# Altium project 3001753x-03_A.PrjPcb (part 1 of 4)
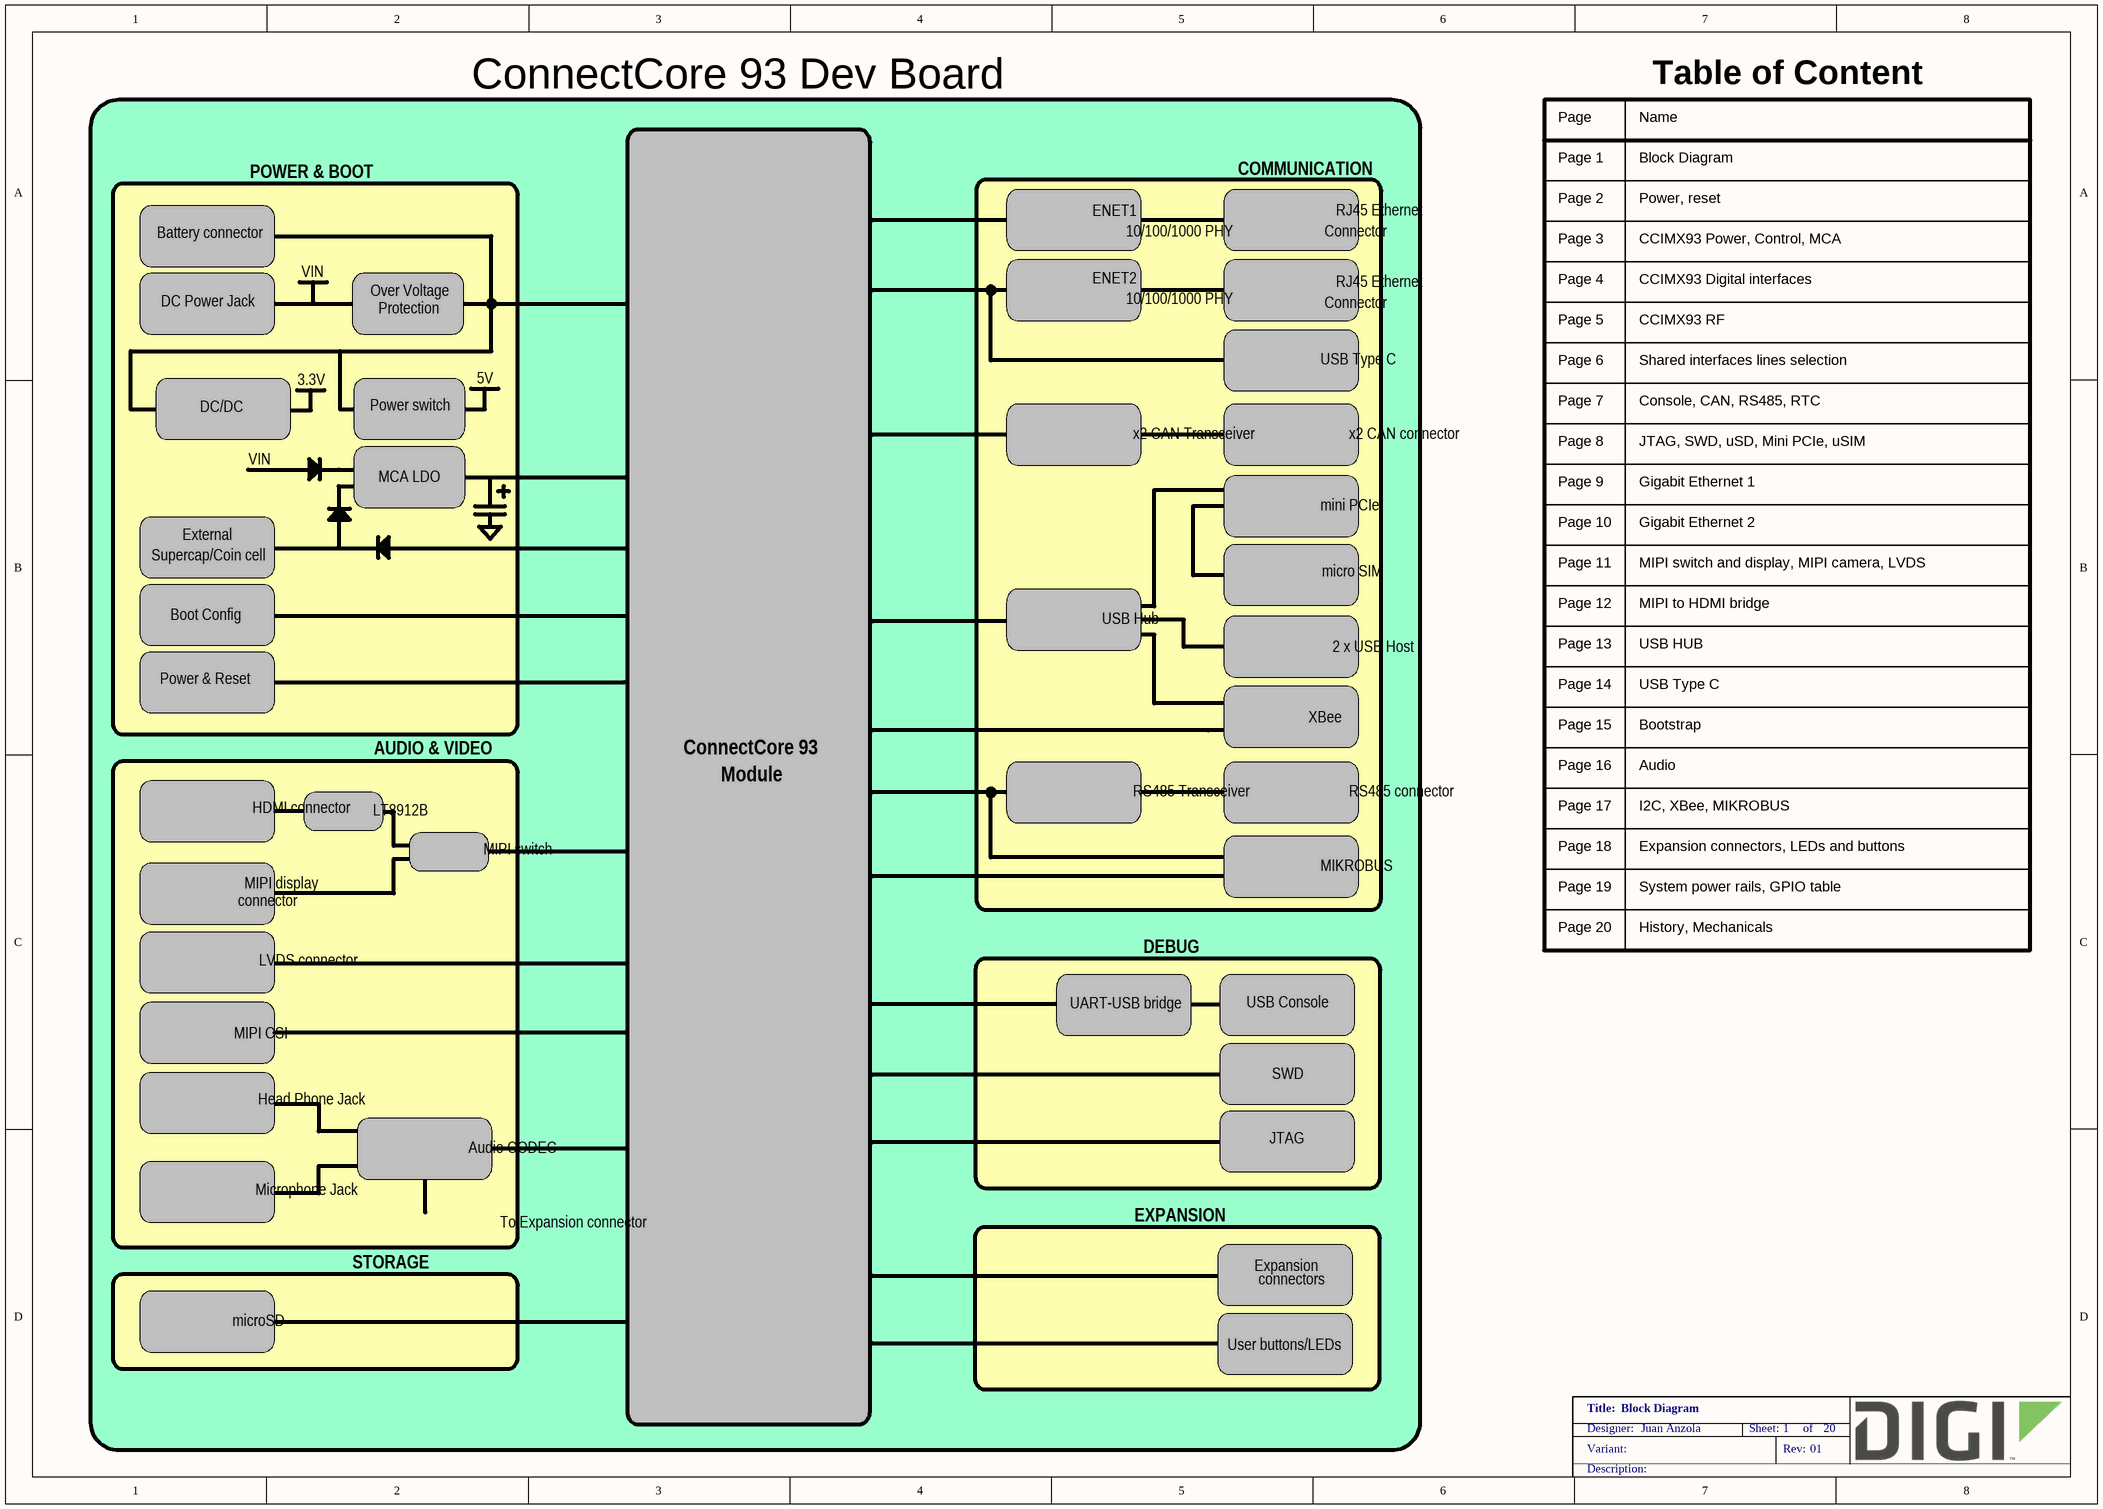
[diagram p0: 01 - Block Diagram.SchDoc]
VariantRevision: 01
20 sheets, 677 parts. Net scope: flat (ports and power ports of the same name join across sheets).
Board files: 3001753x-03_A.PcbDoc, 3001753x-03_A_IND.PcbDoc, 3001753x-03_A_PANEL.PcbDoc
Sheets:
  01 - Block Diagram.SchDoc
  02 - Power, reset.SchDoc
  03 - CCIMX93 Power, Control, MCA.SchDoc
  04 - CCIMX93 Digital interfaces.SchDoc
  05 - CCIMX93 RF.SchDoc
  06 - Shared interfaces lines selection.SchDoc
  07 - Console, CAN, RS485, RTC.SchDoc
  08 - JTAG, SWD, uSD, Mini PCIe, uSIM.SchDoc
  09 - Gigabit Ethernet 1.SchDoc
  10 - Gigabit Ethernet 2.SchDoc
  11 - MIPI switch and display, MIPI camera, LVDS.SchDoc
  12 - MIPI to HDMI bridge.SchDoc
  13 - USB HUB.SchDoc
  14 - USB Type C.SchDoc
  15 - Bootstrap.SchDoc
  16 - Audio.SchDoc
  17 - I2C, XBee, MIKROBUS.SchDoc
  18 - Expansion connectors, LEDs and buttons.SchDoc
  19 - System power rails, GPIO table.SchDoc
  20 - History, Mechanicals.SchDoc

## Sheet 01 - Block Diagram.SchDoc: Block Diagram
size A3; PageSetup: Record=PageOptions¦CenterHorizontal=True¦CenterVertical=True¦PrintScale=0.70¦XCorrection=1.00¦YCorrection=1.00¦PrintKind=0¦BorderSize=5000000¦LeftOffset=0¦BottomOffset=0¦Orientation=2¦PaperLength=4200¦PaperWidth=2970¦Scale=100¦PaperSource=7¦PrintQuality=600¦MediaType=1¦DitherType=10¦PaperKind=A4¦PrintScaleMode=1; Author: Juan Anzola; SheetNumber: 1; SheetTotal: 20

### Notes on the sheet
- ConnectCore 93 Dev Board
- Table of Content
- POWER & BOOT
- COMMUNICATION
- Page 1
- Page
- Block Diagram
- Name
- Battery connector
- ENET1
- 10/100/1000 PHY
- Connector
- RJ45 Ethernet
- Page 2
- Page 3
- Power, reset
- CCIMX93 Power, Control, MCA
- DC Power Jack
- VIN
- Protection
- Over Voltage
- ENET2
- Page 4
- CCIMX93 Digital interfaces
- 5V
- USB Type C
- Page 5
- Page 6
- CCIMX93 RF
- Shared interfaces lines selection
- DC/DC
- 3.3V
- Power switch
- x2 CAN Transceiver
- x2 CAN connector
- Page 7
- Page 8
- JTAG, SWD, uSD, Mini PCIe, uSIM
- Console, CAN, RS485, RTC
- MCA LDO
- mini PCIe
- Page 9
- Gigabit Ethernet 1
- Supercap/Coin cell
- External
- micro SIM
- Page 10
- Page 11
- Gigabit Ethernet 2
- MIPI switch and display, MIPI camera, LVDS
- Boot Config
- USB Hub
- 2 x USB Host
- Page 12
- Page 13
- USB HUB
- MIPI to HDMI bridge
- Power & Reset
- XBee
- Page 14
- AUDIO & VIDEO
- ConnectCore 93
- Module
- Page 15
- Page 16
- Audio
- Bootstrap
- HDMI connector
- LT8912B
- MIPI switch
- RS485 Transceiver
- RS485 connector
- Page 17
- Page 18
- I2C, XBee, MIKROBUS
- Expansion connectors, LEDs and buttons
- connector
- MIPI display
- MIKROBUS
- Page 19
- System power rails, GPIO table
- LVDS connector
- DEBUG
- Page 20
- History, Mechanicals
- MIPI CSI
- UART-USB bridge
- USB Console
- Head Phone Jack
- SWD
- Audio CODEC
- JTAG
- Microphone Jack
- To Expansion connector
- EXPANSION
- microSD
- STORAGE
- Expansion
- connectors
- User buttons/LEDs

## Sheet 02 - Power, reset.SchDoc: Power, reset
size A3; PageSetup: Record=PageOptions¦CenterHorizontal=True¦CenterVertical=True¦PrintScale=0.70¦XCorrection=1.00¦YCorrection=1.00¦PrintKind=0¦BorderSize=5000000¦LeftOffset=0¦BottomOffset=0¦Orientation=2¦PaperLength=4200¦PaperWidth=2970¦Scale=100¦PaperSource=7¦PrintQuality=600¦MediaType=1¦DitherType=10¦PaperKind=A4¦PrintScaleMode=1; Author: Juan Anzola; SheetNumber: 2; SheetTotal: 20
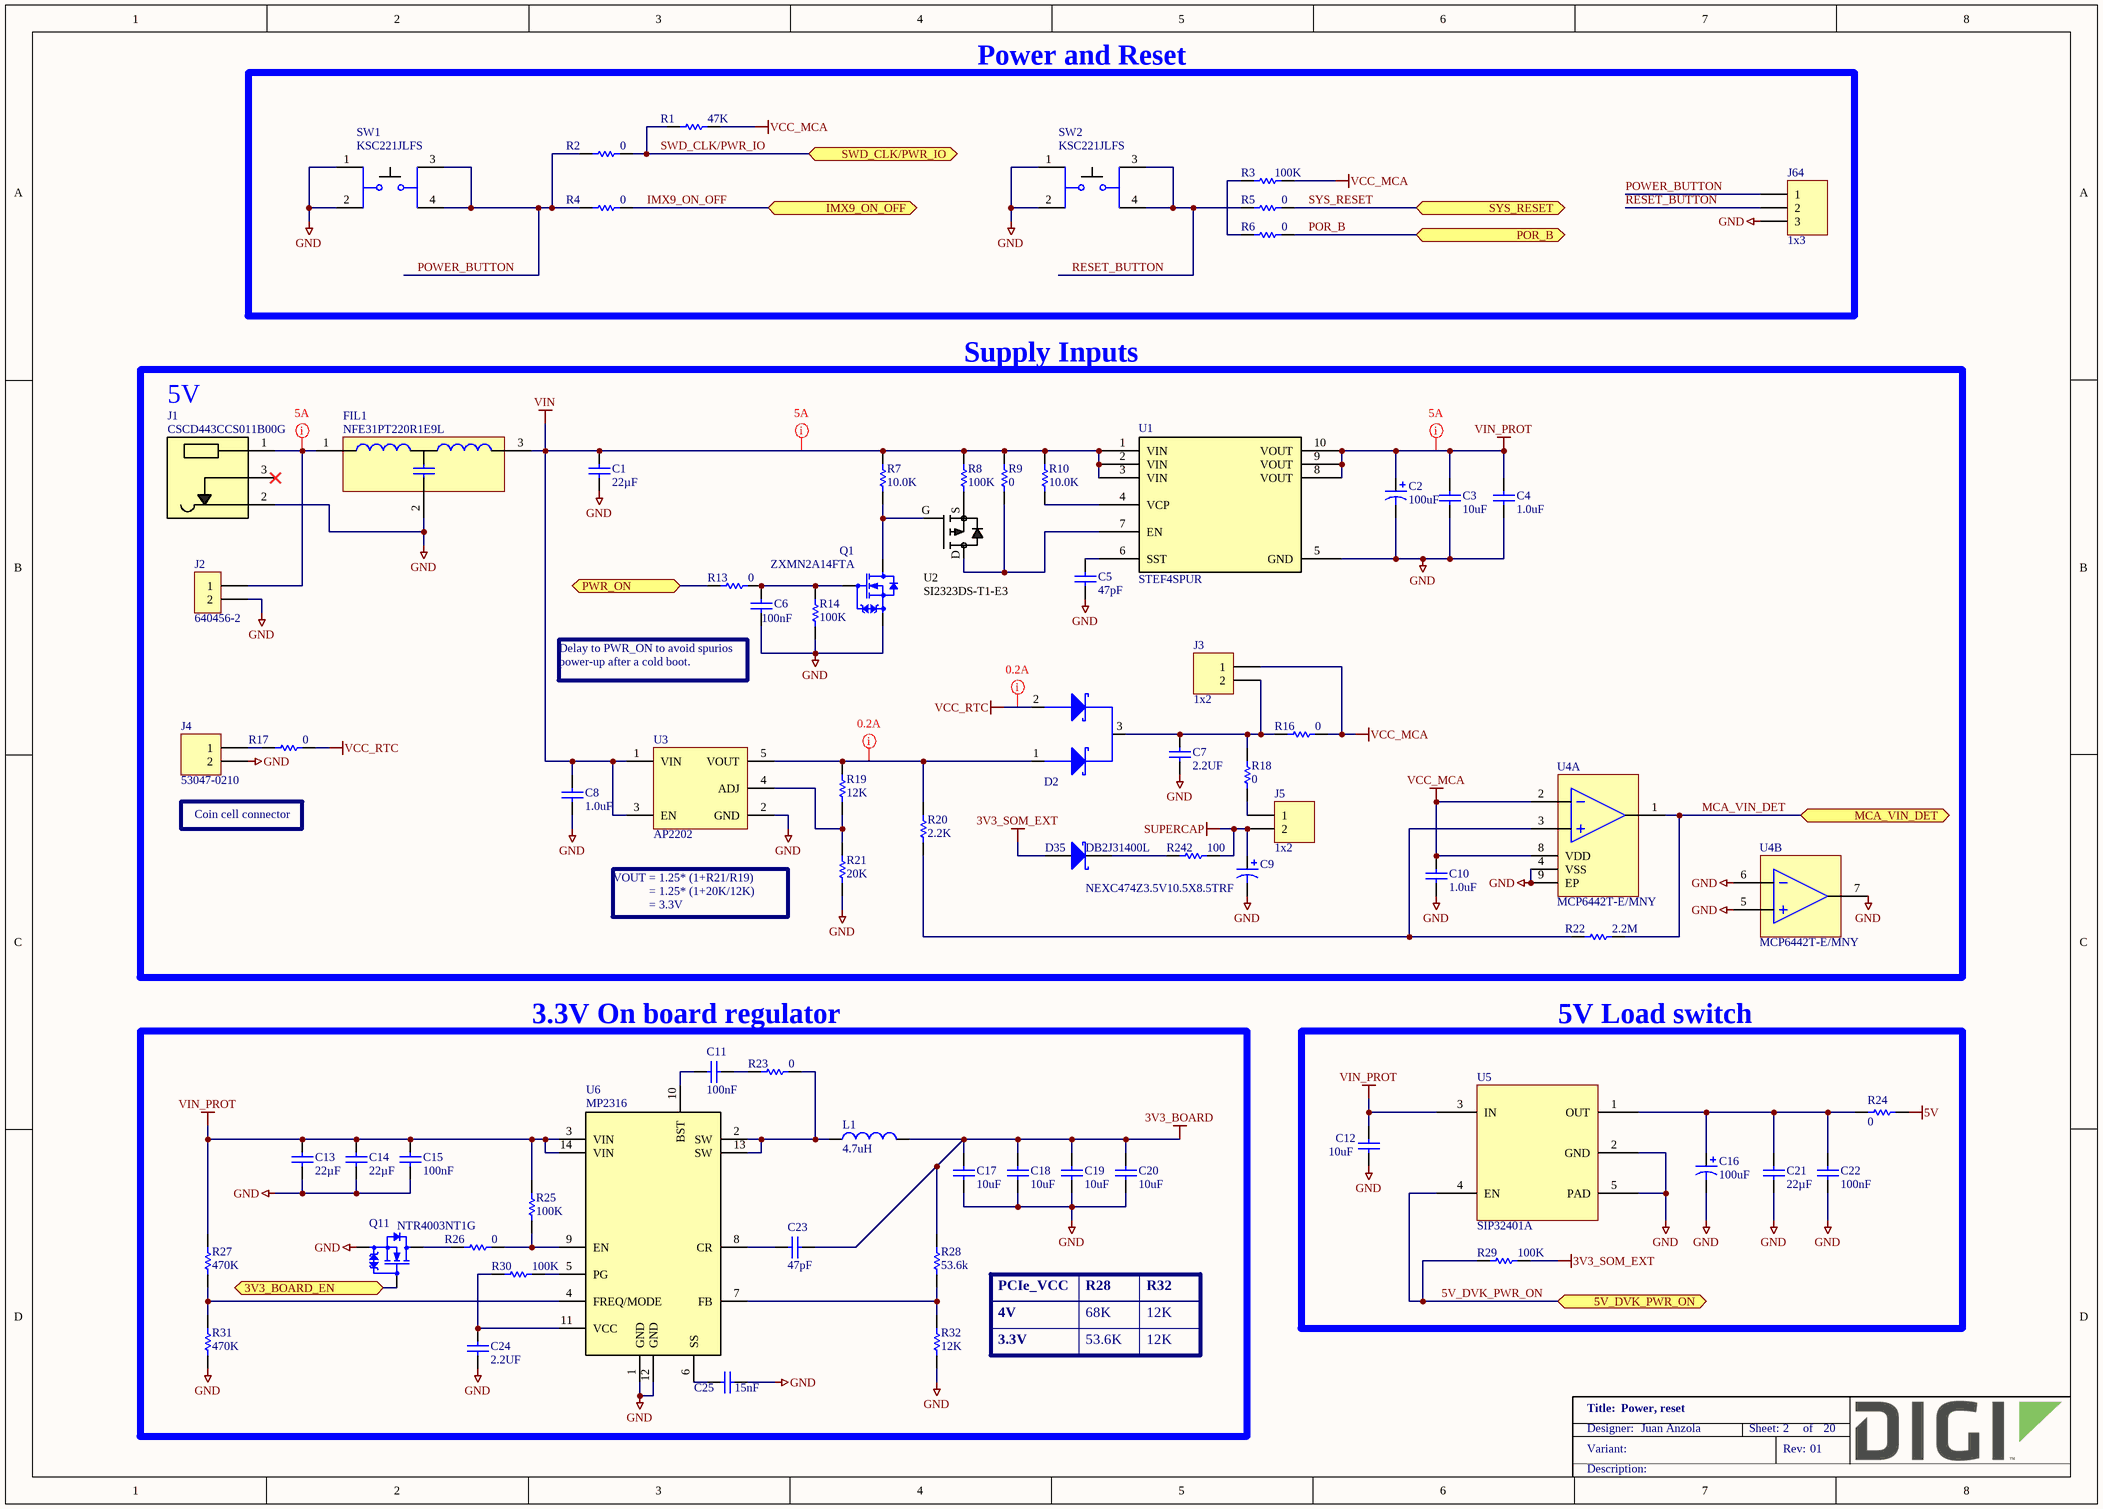
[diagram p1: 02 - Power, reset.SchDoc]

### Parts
C1  22µF  [CAPC1608X90N]
C2  100uF  [CAPMP3216X120N]
C3  10uF  [CAPC1005X55N]
C4  1.0uF  [CAPC1005X55N]
C5  47pF  [CAPC1005X55N]
C6  100nF  [CAPC1005X55N]
C7  2.2UF  [CAPC1608X90N]
C8  1.0uF  [CAPC1005X55N]
C9  NEXC474Z3.5V10.5X8.5TRF  [NEXC474Z3.5V10.5X8.5TRF]
C10  1.0uF  [CAPC1005X55N]
C11  100nF  [CAPC1005X55N]
C12  10uF  [CAPC1005X55N]
C13  22µF  [CAPC1608X90N]
C14  22µF  [CAPC1608X90N]
C15  100nF  [CAPC1005X55N]
C16  100uF  [CAPMP3216X120N]
C17  10uF  [CAPC2013X135N]
C18  10uF  [CAPC2013X135N]
C19  10uF  [CAPC2013X135N]
C20  10uF  [CAPC2013X135N]
C21  22µF  [CAPC1608X90N]
C22  100nF  [CAPC1005X55N]
C23  47pF  [CAPC1005X55N]
C24  2.2UF  [CAPC1608X90N]
C25  15nF  [CAPC1005X55N]
D2  BAT54CWT1G  [SOT65P210X100-3AN]  (value not drawn)
D35  DB2J31400L  [SODFL2513X80N]
FIL1  NFE31PT220R1E9L  [FIL_NFE31P]
J1  CSCD443CCS011B00G  [conn_CSCD443CCS011B00G]
J2  640456-2  [TE_640456-2]
J3  1x2  [FCI_68002-102HLF]
J4  Manufacturer_Part_Number: 53047-0210  [MOLEX_53047-0210_Flex]  (hidden comment: 1x2P)
J5  1x2  [FCI_68002-102HLF]
J64  1x3  [SAMTEC_TSW-103-07-G-S]
L1  4.7uH  [IND_DG6045C]
Q1  ZXMN2A14FTA  [SOT95P240X110_GSD-3N]
Q11  NTR4003NT1G  [SOT95P240X110_GSD-3N]
R1  47K  [RESC1005X40N]
R2  0  [RESC1005X40N]
R3  100K  [RESC1005X40N]
R4  0  [RESC1005X40N]
R5  0  [RESC1005X40N]
R6  0  [RESC1005X40N]
R7  10.0K  [RESC1005X40N]
R8  100K  [RESC1005X40N]
R9  0  [RESC1005X40N]
R10  10.0K  [RESC1005X40N]
R13  0  [RESC1005X40N]
R14  100K  [RESC1005X40N]
R16  0  [RESC1609X55N]
R17  0  [RESC1609X55N]
R18  0  [RESC1005X40N]
R19  12K  [RESC1609X55N]
R20  2.2K  [RESC1005X40N]
R21  20K  [RESC1609X55N]
R22  2.2M  [RESC0603X28N]
R23  0  [RESC1609X55N]
R24  0  [RESC1609X55N]
R25  100K  [RESC1005X40N]
R26  0  [RESC1005X40N]
R27  470K  [RESC1005X40N]
R28  53.6k  [RESC1609X55N]
R29  100K  [RESC1005X40N]
R30  100K  [RESC1005X40N]
R31  470K  [RESC1005X40N]
R32  12K  [RESC1609X55N]
R242  100  [RESC1005X40N]
SW1  KSC221JLFS  [SW_KSC221J]
SW2  KSC221JLFS  [SW_KSC221J]
U1  STEF4SPUR  [SON50P300X300X80-11T164X238N]
U2  SI2323DS-T1-E3  [SOT95P240X110_GSD-3N]
U3  AP2202  [SOT95P280X145-5N]
U4  MCP6442T-E/MNY  [SON50P300X200X80-9N]  (parts A,B of 2)
U5  SIP32401A  [SON50P120X160X60-5T55X91N]
U6  MP2316  [QFN_MPS_MP2316]

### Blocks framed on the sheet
Power and Reset: J64 R1-R6 SW1 SW2
Supply Inputs: C1-C10 D2 D35 FIL1 J1-J5 Q1 R7-R10 R13 R14 R16-R22 R242 U1-U4
3.3V On board regulator: C11 C13-C15 C17-C20 C23-C25 L1 Q11 R23 R25-R28 R30-R32 U6
5V Load switch: C12 C16 C21 C22 R24 R29 U5

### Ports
3V3_BOARD_EN (bidir), 5V_DVK_PWR_ON (bidir), IMX9_ON_OFF (bidir), MCA_VIN_DET (bidir), POR_B (bidir), PWR_ON (bidir), SWD_CLK/PWR_IO (bidir), SYS_RESET (bidir)

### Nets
3V3_BOARD: C17.2 C18.2 C19.2 C20.2 C23.2 L1.2 R28.2
3V3_SOM_EXT: D35.A R29.2
5V: R24.2
GND: C1.1 C2.2 C3.1 C4.1 C5.1 C6.2 C7.1 C8.1 C9.2 C10.2 C12.1 C13.1 C14.1 C15.1 C16.2 C17.1 C18.1 C19.1 C20.1 C21.1 C22.1 C24.1 C25.1 FIL1.2 J1.2 J2.2 J4.2 J64.3 Q1.S Q11.S R14.2 R21.1 R31.1 R32.1 SW1.1 SW1.2 SW2.1 SW2.2 U1.5(GND) U3.2(GND) U4.4(VSS) U4.5(VINB+) U4.6(VINB-) U4.7(VOUTB) U4.9(EP) U5.2(GND) U5.5(PAD) U6.1(GND) U6.12(GND)
SUPERCAP: C9.1 J5.2 R242.1
VCC_MCA: C10.1 J3.1 R1.2 R3.2 R16.2 U4.2(VIN-) U4.8(VDD)
VCC_RTC: D2.2 R17.2
VIN: C1.2 C8.2 FIL1.3(GND) R7.2 R8.2 R9.2 R10.2 U1.1(VIN) U1.2(VIN) U1.3(VIN) U3.1(VIN) U3.3(EN)
VIN_PROT: C2.1 C3.2 C4.2 C12.2 C13.2 C14.2 C15.2 R25.2 R27.2 U1.8(VOUT) U1.9(VOUT) U1.10(VOUT) U5.3(IN) U6.3(VIN) U6.14(VIN)
3V3_BOARD_EN: Q11.G ; port 3V3_BOARD_EN
5V_DVK_PWR_ON: R29.1 U5.4(EN) ; port 5V_DVK_PWR_ON
IMX9_ON_OFF: R4.2 ; port IMX9_ON_OFF
MCA_VIN_DET: R22.2 U4.1(VOUT) ; port MCA_VIN_DET
POR_B: R6.2 ; port POR_B
POWER_BUTTON: J64.1 R2.1 R4.1 SW1.3 SW1.4
PWR_ON: R13.1 ; port PWR_ON
RESET_BUTTON: J64.2 R5.1 SW2.3 SW2.4
SWD_CLK/PWR_IO: R1.1 R2.2 ; port SWD_CLK/PWR_IO
SYS_RESET: R5.2 ; port SYS_RESET
NetC5_2: C5.2 U1.6(SST)
NetC6_1: C6.1 Q1.G R13.2 R14.1
NetC7_2: C7.2 D2.3 J3.2 R16.1 R18.2
NetC11_1: C11.1 U6.10(BST)
NetC11_2: C11.2 R23.1
NetC16_1: C16.1 C21.2 C22.2 R24.1 U5.1(OUT)
NetC23_1: C23.1 U6.8(CR)
NetC24_2: C24.2 R30.1 U6.11(VCC)
NetC25_2: C25.2 U6.6(SS)
NetD2_1: D2.1 R19.2 R20.2 U3.5(VOUT)
NetD35_K: D35.K R242.2
NetFIL1_1: FIL1.1(GND) J1.1 J2.1
NetJ4_1: J4.1 R17.1
NetJ5_1: J5.1 R18.1
NetL1_1: L1.1 R23.2 U6.2(SW) U6.13(SW)
NetQ1_D: Q1.D R7.1 U2.G
NetQ11_D: Q11.D R26.1
NetR3_1: R3.1 R6.1
NetR8_1: R8.1 U2.S
NetR9_1: R9.1 U1.7(EN) U2.D
NetR10_1: R10.1 U1.4(VCP)
NetR19_1: R19.1 R21.2 U3.4(ADJ)
NetR20_1: R20.1 R22.1 U4.3(VIN+)
NetR25_1: R25.1 R26.2 U6.9(EN)
NetR27_1: R27.1 R31.2 U6.4(FREQ/MODE)
NetR28_1: R28.1 R32.2 U6.7(FB)
NetR30_2: R30.2 U6.5(PG)

Not connected (* = marked no-connect by the designer): J1 3*

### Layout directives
net class 0.2A: NetD2_1, VCC_RTC
net class 5A: NetFIL1_1, VIN, VIN_PROT

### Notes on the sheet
- 5V
- (near C6) Delay to PWR_ON to avoid spurios
  power-up after a cold boot.
- Coin cell connector
- VOUT = 1.25* (1+R21/R19)
  = 1.25* (1+20K/12K)
  = 3.3V
- PCIe_VCC
- 4V
- R28
- 68K
- R32
- 12K
- 3.3V
- 53.6K

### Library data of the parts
C1 = 1000998: CAP CER 22UF 10V 20% X5R 0603; Part_Type: Capacitor; Manufacturer: Samsung; Manufacturer_Part_Number: CL10A226MP8NUNE; Manufacturer_Alt_1: TDK Corporation; Manufacturer_Alt_1_Part_Number: C1608X5R1A226M080AC; Digi_PN: 14050684; Component_Life_Cycle_State: Reviewed; Area: 2,27; Tolerance: 20
C2 C16 = 1001196: CAP TANT 100UF 6.3V 20% 1206; Part_Type: Capacitor; Manufacturer: Rohm; Manufacturer_Part_Number: TCTAL0J107M8R; Digi_PN: 14050490; Component_Life_Cycle_State: Reviewed; Area: 8.01; Project: CCWMX6_SBC board
C3 C12 = 1001168: CAP CER 10UF 10V 20% X5R 0402; Part_Type: Capacitor; Manufacturer: Samsung; Manufacturer_Part_Number: CL05A106MP5NUNC; Digi_PN: 14050689; Component_Life_Cycle_State: Reviewed; Area: 0.95; Project: CCWMX6_SBC board
C4 = 1001167: CAP CER 1UF 10V 10% X5R 0402; Part_Type: Capacitor; Manufacturer: Murata; Manufacturer_Part_Number: GRM155R61A105KE15D; Digi_PN: 14050399; Component_Life_Cycle_State: Reviewed; Area: 0,95; Project: CCWMX6_SBC board
C5 = 1000007: CAP 47pF 50V 5% NP0 0402; Part_Type: Capacitor; Manufacturer: Murata; Manufacturer_Part_Number: GRM1555C1H470JA01D; Manufacturer_Alt_1: AVX Corporation; Manufacturer_Alt_1_Part_Number: 04025A470JAT2A; Note: 14050747 is Digi No. for GE WDNU; Digi_PN: 14050309; Component_Life_Cycle_State: CAD Reviewed; Area: 0,95; Temp_Coef: C0G, NP0
C6 C22 = 1000006: CAP 100nF 16V 10% X7R 0402; Part_Type: Capacitor; Manufacturer: Murata; Manufacturer_Part_Number: GRM155R71C104KA88D; Component_Life_Cycle_State: CAD Reviewed; Area: 0.95; Project: KITT; Tolerance: 10; Digi_PN: 14050552
C7 C24 = 1001303: CAP CER 2.2UF 16V 10% X5R 0603; Part_Type: Capacitor; Manufacturer: TDK Corporation; Manufacturer_Part_Number: C1608X5R1C225K080AB; Digi_PN: 14050730; Component_Life_Cycle_State: Reviewed; Area: 2,27; Project: Pinnacle
C8 C10 = 1001167: CAP CER 1UF 10V 10% X5R 0402; Part_Type: Capacitor; Manufacturer: Murata; Manufacturer_Part_Number: GRM155R61A105KE15D; Digi_PN: 14050399; Component_Life_Cycle_State: Reviewed; Area: 0,95
C9 = 1002775: SMCAP, 0.47F 3.5V SUPERCAP 8.5x10.5x10.8mm SMT; Part_Type: Capacitor; Manufacturer: NIC; Digi_PN: 14050629; Component_Life_Cycle_State: Pending
C11 C15 = 1000006: CAP 100nF 16V 10% X7R 0402; Part_Type: Capacitor; Manufacturer: Murata; Manufacturer_Part_Number: GRM155R71C104KA88D; Digi_PN: 14050552; Component_Life_Cycle_State: CAD Reviewed; Area: 0.95; Project: KITT; Tolerance: 10
C13 C14 C21 = 1000998: CAP CER 22UF 10V 20% X5R 0603; Part_Type: Capacitor; Manufacturer: Samsung; Manufacturer_Part_Number: CL10A226MP8NUNE; Manufacturer_Alt_1: TDK Corporation; Manufacturer_Alt_1_Part_Number: C1608X5R1A226M080AC; Digi_PN: 14050684; Component_Life_Cycle_State: Reviewed; Area: 2.27; Project: ConnectCore i.MX6 module; Tolerance: 20
C17-C20 = 1000111: CAP CER 10UF 16V 10% X5R 0805; Part_Type: Capacitor; Manufacturer: Murata; Manufacturer_Part_Number: GRM21BR61C106KE15L; Digi_PN: 14050701; Component_Life_Cycle_State: Proven; Area: 3.99; Project: Adjustable Foundation; Tolerance: 10
C23 = 1000007: CAP 47pF 50V 5% NP0 0402; Part_Type: Capacitor; Manufacturer: Murata; Manufacturer_Part_Number: GRM1555C1H470JA01D; Manufacturer_Alt_1: AVX Corporation; Manufacturer_Alt_1_Part_Number: 04025A470JAT2A; Note: 14050747 is Digi No. for GE WDNU; Digi_PN: 14050309; Component_Life_Cycle_State: CAD Reviewed; Area: 0.95; Project: KITT; Temp_Coef: C0G, NP0
C25 = 1000512: CAP CER 0.015UF 16V 10% X7R 0402; Part_Type: Capacitor; Manufacturer: Murata; Manufacturer_Part_Number: GRM155R71C153KA01D; Digi_PN: 14050713; Component_Life_Cycle_State: CAD Reviewed; Area: 0.95; Project: Cellular Proof of Concept
D2 = 1000794: DIODE SCHOTTKY 30V 200MA SOT323; Part Number: SDS1920004; Manufacturer: Fairchild Semiconductor; Manufacturer Alt 1: none; Manufacturer Part Num: 0082610201; Part_Type: Diodes; Digi_PN: 17050561; Component_Life_Cycle_State: CAD Reviewed; Area: 7,68; Project: SmartMeter2
D35 = 1002592: DIODE SCHOTTKY 30V 30MA SMINI2; Part_Type: Diodes; Manufacturer: Panasonic - ECG; Digi_PN: 17000142; Component_Life_Cycle_State: Reviewed; Area: 6,06
FIL1 = 1002745: FILTER LC(T) 22PF SMD; Manufacturer: Murata; Digi_PN: 21000602; Component_Life_Cycle_State: Created; Area: 15
J1 = 1001105: DC Power Jack; Part_Type: Connector; Manufacturer: Bobbintron Electrical Corp; Digi_PN: 18000302; Component_Life_Cycle_State: Reviewed; Area: 137; Project: CCWMX6_SBC board
J2 = 1002003: CONN HEADER VERT 2POS .100 TIN; Part_Type: Connector; Manufacturer: TE Connectivity; Digi_PN: 18050128; Component_Life_Cycle_State: Created; Area: 29,05; Project: iMX6UL+PMIC
J3 J5 = 1001128: CONN HEADER 2POS .100" SGL GOLD; Part_Type: Connector; Manufacturer: Samtec; Manufacturer_Part_Number: TSW-102-07-G-S; Digi_PN: 00120002; Component_Life_Cycle_State: Reviewed; Area: 12,9032
J4 = 1001136: CONN HEADER 2POS 1.25MM VERT TIN; Part_Type: Connector; Manufacturer: Molex; Component_Life_Cycle_State: Reviewed; Area: 13.6; Project: CCWMX6_SBC board; Digi_PN: 18050343
J64 = 1002832: CONN HEADER 3POS .100" SGL GOLD; Part_Type: Connector; Manufacturer: Samtec; Manufacturer_Part_Number: TSW-103-07-G-S; Digi_PN: 00120003; Component_Life_Cycle_State: Pending; Area: 19,3548
L1 = 1002747: FIXED IND 4.7UH 4.5A 27.6 MOHM; Manufacturer: Murata; Manufacturer_Part_Number: 1255AY-4R7M=P3; Digi_PN: 21000603; Component_Life_Cycle_State: Reviewed; Area: 49
Q1 = 1002855: MOSFET N-CH 20V 3.4A SOT23-3; Part_Type: Transistor; Manufacturer: Diodes, Inc.; Digi_PN: 17000304; Component_Life_Cycle_State: Pending
Q11 = 1000306: MOSFET N-CH 30V 500MA SOT-23; Part_Type: Transistor; Manufacturer: On Semiconductor; Digi_PN: 17050809; Component_Life_Cycle_State: Proven; Area: 10,92
R1 = 1001155: RES 47.0K OHM 1/16W 1% 0402 SMD; Part_Type: Resistor; Manufacturer: Vishay Dale; Manufacturer_Part_Number: CRCW040247K0FKED; Digi_PN: 13050646; Component_Life_Cycle_State: Reviewed; Area: 0.95; Project: CCWMX6_SBC board
R2 R4-R6 R13 R26 = 1000076: RES 0.0 OHM 1/10W 0402 SMD; Part_Type: Resistor; Manufacturer: Panasonic - ECG; Manufacturer_Part_Number: ERJ-2GE0R00X; Component_Life_Cycle_State: Proven; Area: 0.95; Project: Adjustable Foundation; Power_WV_SRF: 10; Digi_PN: 13050387
R3 = 1000480: RES 100K OHM 1/10W 1% 0402 SMD; Part_Type: Resistor; Manufacturer: Panasonic - ECG; Manufacturer_Part_Number: ERJ-2RKF1003X; Digi_PN: 13051063; Component_Life_Cycle_State: CAD Reviewed; Area: 0,95; Project: KITT; Power_WV_SRF: 100
R7 R10 = 1000537: RES 10.0K OHM 1/10W 1% 0402 SMD; Part_Type: Resistor; Manufacturer: Panasonic - ECG; Manufacturer_Part_Number: ERJ-2RKF1002X; Component_Life_Cycle_State: CAD Reviewed; Area: 0.95; Project: KITT; Power_WV_SRF: 100; Digi_PN: 13051084
R8 = 1000480: RES 100K OHM 1/10W 1% 0402 SMD; Part_Type: Resistor; Manufacturer: Panasonic - ECG; Manufacturer_Part_Number: ERJ-2RKF1003X; Digi_PN: 13051063; Component_Life_Cycle_State: CAD Reviewed; Area: 0,95; Power_WV_SRF: 100
R9 R18 = 1000076: RES 0.0 OHM 1/10W 0402 SMD; Part_Type: Resistor; Manufacturer: Panasonic - ECG; Manufacturer_Part_Number: ERJ-2GE0R00X; Digi_PN: 13050387; Component_Life_Cycle_State: Proven; Area: 0,95; Power_WV_SRF: 10
R14 R25 R29 R30 = 1000480: RES 100K OHM 1/10W 1% 0402 SMD; Part_Type: Resistor; Manufacturer: Panasonic - ECG; Manufacturer_Part_Number: ERJ-2RKF1003X; Digi_PN: 13051063; Component_Life_Cycle_State: CAD Reviewed; Area: 0.95; Project: KITT; Power_WV_SRF: 100
R16 R17 R23 = 1000208: RES 0.0 OHM 1/10W 0603; Part_Type: Resistor; Manufacturer: Panasonic - ECG; Manufacturer_Part_Number: ERJ-3GEY0R00V; Note: 13051103 = Digi No. for GE WDNU; Digi_PN: 13050568; Component_Life_Cycle_State: Reviewed; Area: 2,5; Voltage: 75V
R19 = 1001200: RES 12.0K OHM 1/10W 1% 0603 SMD; Part_Type: Resistor; Manufacturer: Yageo; Manufacturer_Part_Number: RC0603FR-0712KL; Digi_PN: 13050531; Component_Life_Cycle_State: Reviewed; Area: 2,5; Project: LuCoV2; Power_WV_SRF: 100; Tolerance: 1
R20 = 1001156: RES 2.20K OHM 1/16W 1% 0402 SMD; Part_Type: Resistor; Manufacturer: Yageo; Manufacturer_Part_Number: RC0402FR-072K2L; Note: 13051099 = Digi No. for GE WDNU; Digi_PN: 13050699; Component_Life_Cycle_State: Reviewed; Area: 0,95
R21 = 1000142: RES 20K OHM 1/10W 5% 0603 SMD; Part_Type: Resistor; Manufacturer: Panasonic - ECG; Manufacturer_Part_Number: ERJ-3GEYJ203V; Digi_PN: 13050013; Component_Life_Cycle_State: Reviewed; Area: 2,5; Project: Adjustable Foundation; Power_WV_SRF: 100; Tolerance: 5
R22 = 1000980: RES 2.2M OHM 1/20W 5% 0201 SMD; Part_Type: Resistor; Manufacturer: Rohm; Manufacturer_Part_Number: MCR006YZPJ225; Manufacturer_Alt_1: Panasonic - ECG; Manufacturer_Alt_1_Part_Number: ERJ-1GEJ225C; Digi_PN: 13050884; Component_Life_Cycle_State: Reviewed; Area: 1,73; Power_WV_SRF: 50; Tolerance: 5
R24 = 1000208: RES 0.0 OHM 1/10W 0603; Part_Type: Resistor; Manufacturer: Panasonic - ECG; Manufacturer_Part_Number: ERJ-3GEY0R00V; Note: 13051103 = Digi No. for GE WDNU; Digi_PN: 13050568; Component_Life_Cycle_State: Reviewed; Area: 2.5; Project: Adjustable Foundation; Voltage: 75V
R27 R31 = 1000701: RES 470K OHM 1/10W 1% 0402 SMD; Part_Type: Resistor; Manufacturer: Panasonic - ECG; Manufacturer_Part_Number: ERJ-2RKF4703X; Digi_PN: 13051092; Component_Life_Cycle_State: CAD Reviewed; Area: 0.95; Project: KITT; Power_WV_SRF: 100
R28 = 1001518: RES 53.6K OHM 1/10W 1% 0603 SMD; Part_Type: Resistor; Manufacturer: Panasonic - ECG; Manufacturer_Part_Number: ERJ-3EKF5362V; Digi_PN: 13051064; Component_Life_Cycle_State: Reviewed; Area: 2.5; Project: WDNU-II
R32 = 1001200: RES 12.0K OHM 1/10W 1% 0603 SMD; Part_Type: Resistor; Manufacturer: Yageo; Manufacturer_Part_Number: RC0603FR-0712KL; Digi_PN: 13050531; Component_Life_Cycle_State: Reviewed; Area: 2.5; Project: LuCoV2; Power_WV_SRF: 100; Tolerance: 1
R242 = 1000467: RES 100 OHM 1/10W 1% 0402 SMD; Part_Type: Resistor; Manufacturer: Panasonic - ECG; Manufacturer_Part_Number: ERJ-2RKF1000X; Digi_PN: 13051087; Component_Life_Cycle_State: CAD Reviewed; Area: 0,95
SW1 SW2 = 1001124: SWITCH TACTILE SPST-NO 0.05A 32V; Manufacturer: ITT; Digi_PN: 22000059; Component_Life_Cycle_State: Reviewed; Area: 37; Project: CCWMX6_SBC board; Note: 22000295 = Digi No. for GE WDNU
U1 = 1002744: IC ELECTRONIC FUSE 10VFDFPN; Manufacturer: STMicroelectronics; Digi_PN: 16000208; Component_Life_Cycle_State: Created; Area: 14,77
U2 = 1001163: MOSFET P-CH 20V 3.7A SOT23-3; Part_Type: IC; Manufacturer: Vishay Siliconix; Digi_PN: 17050358; Component_Life_Cycle_State: Reviewed; Area: 10.92; Project: CCWMX6_SBC board
U3 = 1001979: IC REG LDO ADJ 0.15A SOT25; Part_Type: Regulator; Manufacturer: Diodes, Inc.; Manufacturer_Part_Number: AP2202K-ADJTRG1; Digi_PN: 17050874; Component_Life_Cycle_State: Created; Area: 8,9; Project: iMX6UL+PMIC
U4 = 1000217: IC OPAMP DUAL 1.6V 9KHZ 8TDFN; Manufacturer: Microchip; Digi_PN: 16000212; Component_Life_Cycle_State: Reviewed; Area: 7,4
U5 = 1001857: IC SW W/CTRL SLEW RATE 4TDFN; Manufacturer: Vishay Siliconix; Manufacturer_Part_Number: SIP32401ADNP-T1GE4; Component_Life_Cycle_State: Reviewed; Area: 4.93; Project: CCWMX6_SBC board; Digi_PN: 16052004
U6 = 1001907: IC REG BUCK ADJ 3A SYNC; Manufacturer: Linear Technology; Manufacturer_Part_Number: MP2316GD; Digi_PN: 17050862; Component_Life_Cycle_State: Reviewed; Area: 9.375; Project: CCWMX6_SBC board

## Sheet 03 - CCIMX93 Power, Control, MCA.SchDoc: CCIMX93 Power, Control, MCA
size A3; PageSetup: Record=PageOptions¦CenterHorizontal=True¦CenterVertical=True¦PrintScale=0.70¦XCorrection=1.00¦YCorrection=1.00¦PrintKind=0¦BorderSize=5000000¦LeftOffset=0¦BottomOffset=0¦Orientation=2¦PaperLength=4200¦PaperWidth=2970¦Scale=100¦PaperSource=7¦PrintQuality=600¦MediaType=1¦DitherType=10¦PaperKind=A4¦PrintScaleMode=1; Author: Juan Anzola; SheetNumber: 3; SheetTotal: 20
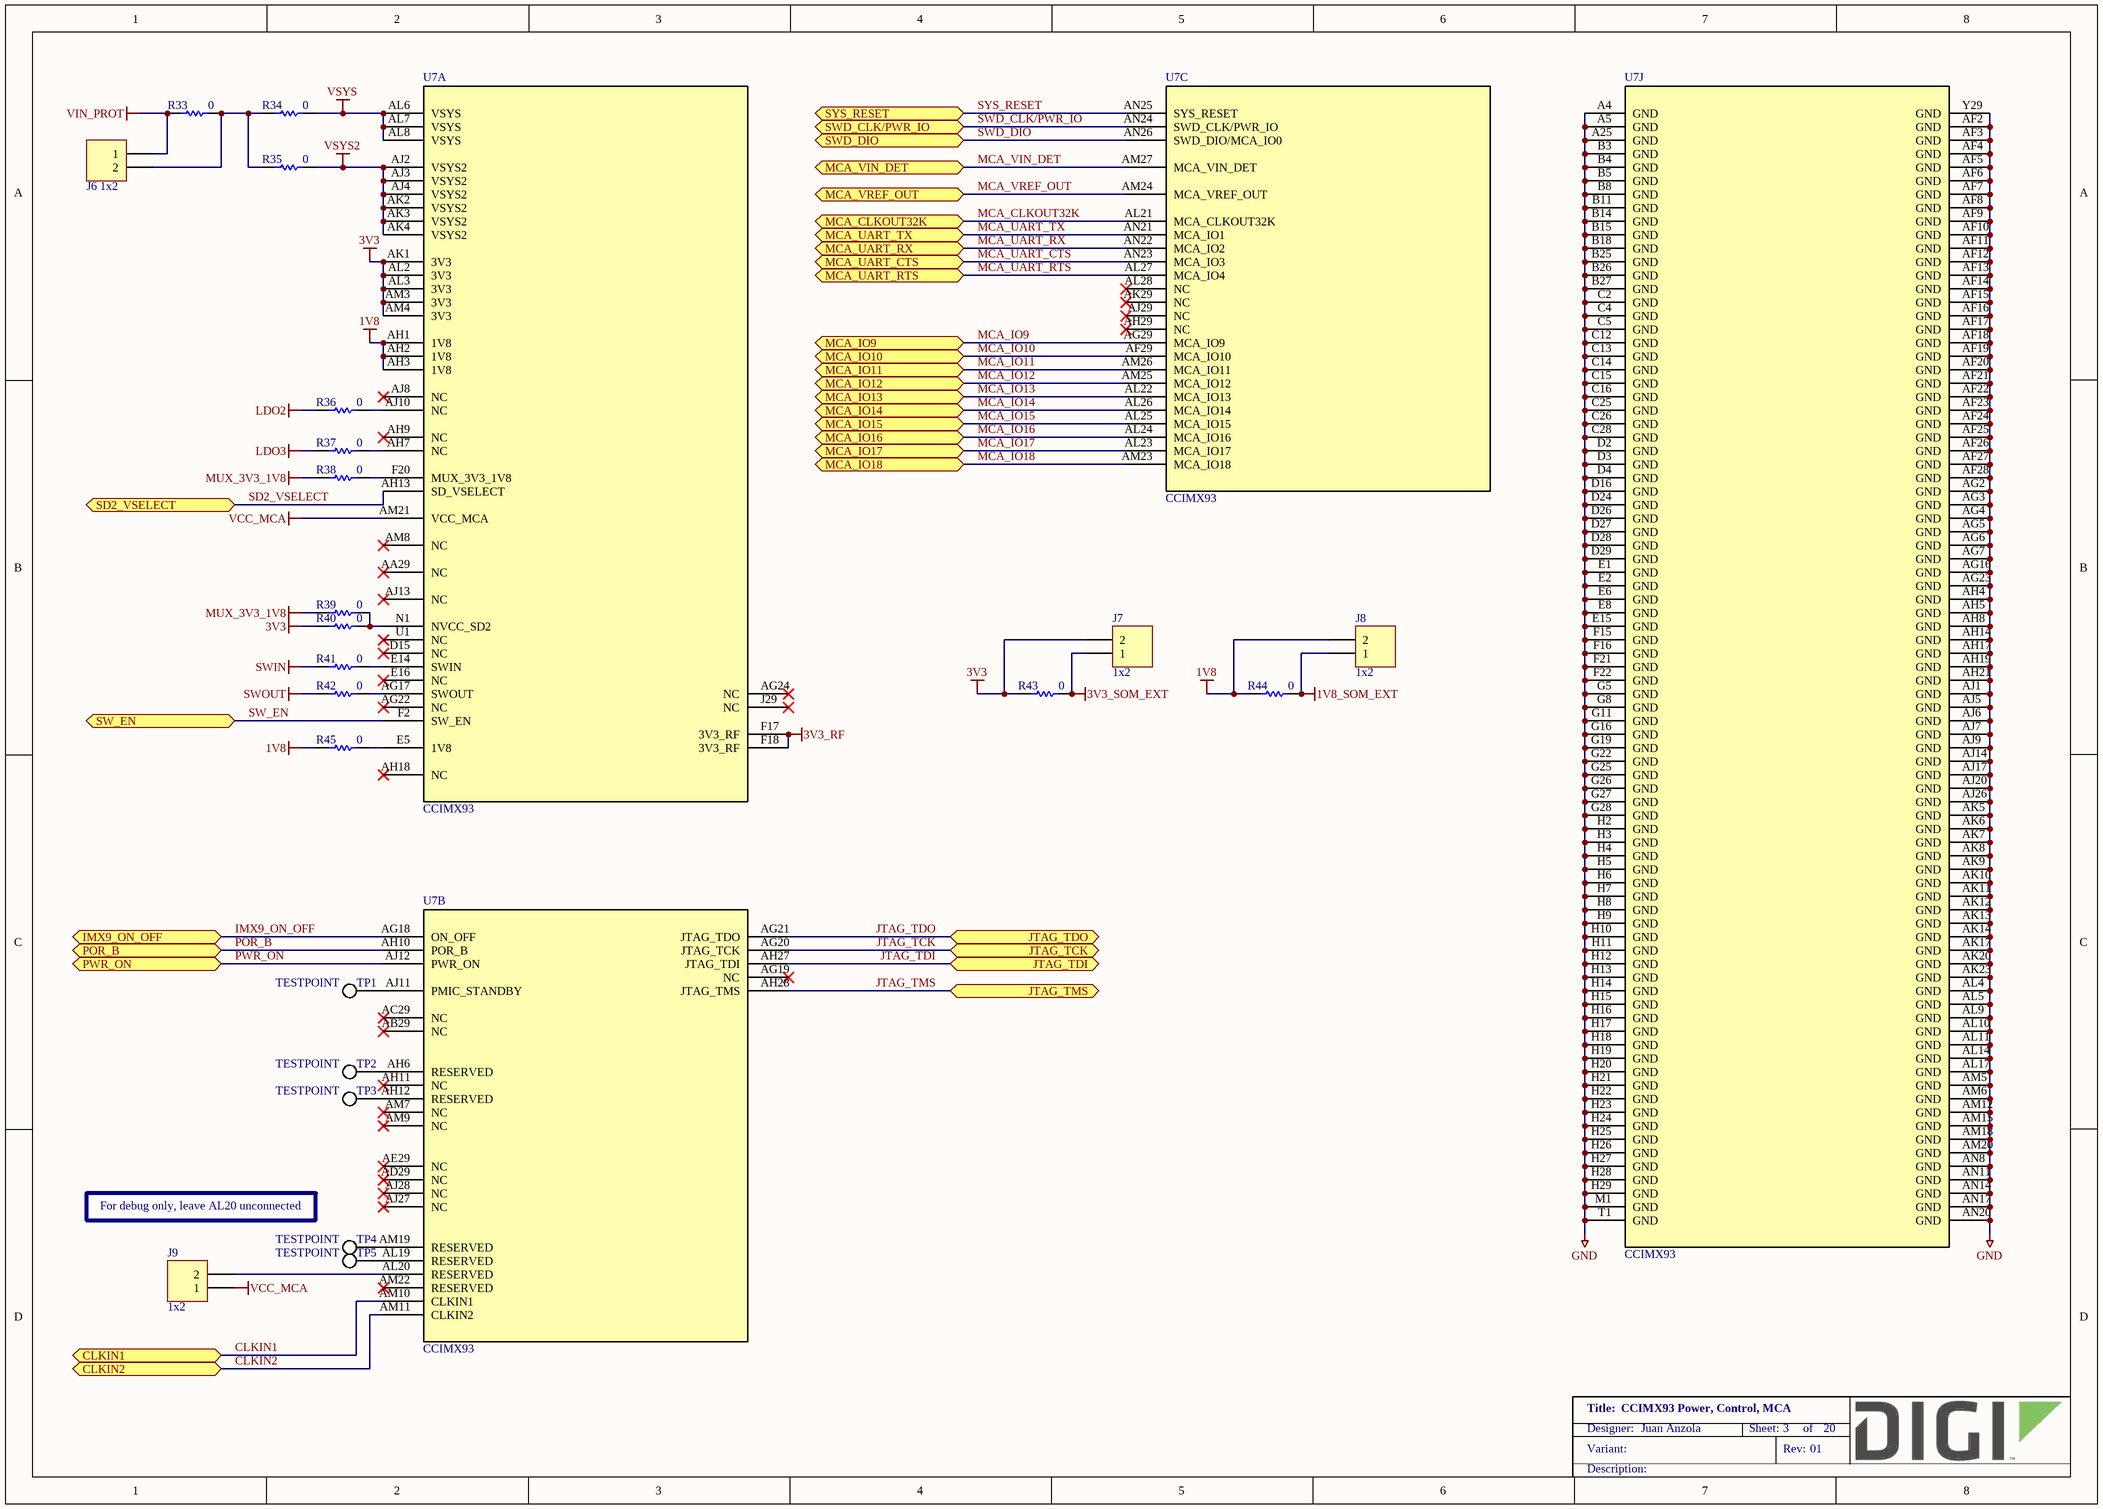
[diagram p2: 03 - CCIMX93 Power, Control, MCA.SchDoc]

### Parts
J6  1x2  [FCI_68002-102HLF]
J7  1x2  [FCI_68002-102HLF]
J8  1x2  [FCI_68002-102HLF]
J9  1x2  [FCI_68002-102HLF]
R33  0  [RESC1609X55N]
R34  0  [RESC1609X55N]
R35  0  [RESC1609X55N]
R36  0  [RESC1005X40N]
R37  0  [RESC1005X40N]
R38  0  [RESC1609X55N]
R39  0  [RESC1005X40N]
R40  0  [RESC1005X40N]
R41  0  [RESC1005X40N]
R42  0  [RESC1005X40N]
R43  0  [RESC1609X55N]
R44  0  [RESC1609X55N]
R45  0  [RESC1005X40N]
TP1  TESTPOINT  [TP0762]  (no BOM)
TP2  TESTPOINT  [TP0762]  (no BOM)
TP3  TESTPOINT  [TP0762]  (no BOM)
TP4  TESTPOINT  [TP0762]  (no BOM)
TP5  TESTPOINT  [TP0762]  (no BOM)
U7  CCIMX93  [CC93_DVK]  (parts A,B,C,J of 10)

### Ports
CLKIN1 (bidir), CLKIN2 (bidir), IMX9_ON_OFF (bidir), JTAG_TCK (bidir), JTAG_TDI (bidir), JTAG_TDO (bidir), JTAG_TMS (bidir), MCA_CLKOUT32K (bidir), MCA_IO9 (bidir), MCA_IO10 (bidir), MCA_IO11 (bidir), MCA_IO12 (bidir), MCA_IO13 (bidir), MCA_IO14 (bidir), MCA_IO15 (bidir), MCA_IO16 (bidir), MCA_IO17 (bidir), MCA_IO18 (bidir), MCA_UART_CTS (bidir), MCA_UART_RTS (bidir), MCA_UART_RX (bidir), MCA_UART_TX (bidir), MCA_VIN_DET (bidir), MCA_VREF_OUT (bidir), POR_B (bidir), PWR_ON (bidir), SD2_VSELECT (bidir), SW_EN (bidir), SWD_CLK/PWR_IO (bidir), SWD_DIO (bidir), SYS_RESET (bidir)

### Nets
1V8: J8.2 R44.1 R45.1 U7.AH1(1V8) U7.AH2(1V8) U7.AH3(1V8)
1V8_SOM_EXT: J8.1 R44.2
3V3: J7.2 R40.1 R43.1 U7.AK1(3V3) U7.AL2(3V3) U7.AL3(3V3) U7.AM3(3V3) U7.AM4(3V3)
3V3_RF: U7.F17(3V3_RF) U7.F18(3V3_RF)
3V3_SOM_EXT: J7.1 R43.2
GND: U7.A25(GND) U7.A4(GND) U7.A5(GND) U7.AF2(GND) U7.AF3(GND) U7.AF4(GND) U7.AF5(GND) U7.AF6(GND) U7.AF7(GND) U7.AF8(GND) U7.AF9(GND) U7.AF10(GND) U7.AF11(GND) U7.AF12(GND) U7.AF13(GND) U7.AF14(GND) U7.AF15(GND) U7.AF16(GND) U7.AF17(GND) U7.AF18(GND) U7.AF19(GND) U7.AF20(GND) U7.AF21(GND) U7.AF22(GND) U7.AF23(GND) U7.AF24(GND) U7.AF25(GND) U7.AF26(GND) U7.AF27(GND) U7.AF28(GND) U7.AG2(GND) U7.AG3(GND) U7.AG4(GND) U7.AG5(GND) U7.AG6(GND) U7.AG7(GND) U7.AG16(GND) U7.AG23(GND) U7.AH4(GND) U7.AH5(GND) U7.AH8(GND) U7.AH14(GND) U7.AH17(GND) U7.AH19(GND) U7.AH21(GND) U7.AJ1(GND) U7.AJ5(GND) U7.AJ6(GND) U7.AJ7(GND) U7.AJ9(GND) U7.AJ14(GND) U7.AJ17(GND) U7.AJ20(GND) U7.AJ26(GND) U7.AK5(GND) U7.AK6(GND) U7.AK7(GND) U7.AK8(GND) U7.AK9(GND) U7.AK10(GND) U7.AK11(GND) U7.AK12(GND) U7.AK13(GND) U7.AK14(GND) U7.AK17(GND) U7.AK20(GND) U7.AK23(GND) U7.AL4(GND) U7.AL5(GND) U7.AL9(GND) U7.AL10(GND) U7.AL11(GND) U7.AL14(GND) U7.AL17(GND) U7.AM5(GND) U7.AM6(GND) U7.AM12(GND) U7.AM15(GND) U7.AM18(GND) U7.AM20(GND) U7.AN8(GND) U7.AN11(GND) U7.AN14(GND) U7.AN17(GND) U7.AN20(GND) U7.B3(GND) U7.B4(GND) U7.B5(GND) U7.B8(GND) U7.B11(GND) U7.B14(GND) U7.B15(GND) U7.B18(GND) U7.B25(GND) U7.B26(GND) U7.B27(GND) U7.C2(GND) U7.C4(GND) U7.C5(GND) U7.C12(GND) U7.C13(GND) U7.C14(GND) U7.C15(GND) U7.C16(GND) U7.C25(GND) U7.C26(GND) U7.C28(GND) U7.D2(GND) U7.D3(GND) U7.D4(GND) U7.D16(GND) U7.D24(GND) U7.D26(GND) U7.D27(GND) U7.D28(GND) U7.D29(GND) U7.E1(GND) U7.E2(GND) U7.E6(GND) U7.E8(GND) U7.E15(GND) U7.F15(GND) U7.F16(GND) U7.F21(GND) U7.F22(GND) U7.G5(GND) U7.G8(GND) U7.G11(GND) U7.G16(GND) U7.G19(GND) U7.G22(GND) U7.G25(GND) U7.G26(GND) U7.G27(GND) U7.G28(GND) U7.H2(GND) U7.H3(GND) U7.H4(GND) U7.H5(GND) U7.H6(GND) U7.H7(GND) U7.H8(GND) U7.H9(GND) U7.H10(GND) U7.H11(GND) U7.H12(GND) U7.H13(GND) U7.H14(GND) U7.H15(GND) U7.H16(GND) U7.H17(GND) U7.H18(GND) U7.H19(GND) U7.H20(GND) U7.H21(GND) U7.H22(GND) U7.H23(GND) U7.H24(GND) U7.H25(GND) U7.H26(GND) U7.H27(GND) U7.H28(GND) U7.H29(GND) U7.M1(GND) U7.T1(GND) U7.Y29(GND)
LDO2: R36.1
LDO3: R37.1
MUX_3V3_1V8: R38.1 R39.1
SWIN: R41.1
SWOUT: R42.1
VCC_MCA: J9.1 U7.AM21(VCC_MCA)
VIN_PROT: J6.1 R33.1
VSYS: R34.2 U7.AL6(VSYS) U7.AL7(VSYS) U7.AL8(VSYS)
VSYS2: R35.2 U7.AJ2(VSYS2) U7.AJ3(VSYS2) U7.AJ4(VSYS2) U7.AK2(VSYS2) U7.AK3(VSYS2) U7.AK4(VSYS2)
CLKIN1: U7.AM10(CLKIN1) ; port CLKIN1
CLKIN2: U7.AM11(CLKIN2) ; port CLKIN2
IMX9_ON_OFF: U7.AG18(ON_OFF) ; port IMX9_ON_OFF
JTAG_TCK: U7.AG20(JTAG_TCK) ; port JTAG_TCK
JTAG_TDI: U7.AH27(JTAG_TDI) ; port JTAG_TDI
JTAG_TDO: U7.AG21(JTAG_TDO) ; port JTAG_TDO
JTAG_TMS: U7.AH28(JTAG_TMS) ; port JTAG_TMS
MCA_CLKOUT32K: U7.AL21(MCA_CLKOUT32K) ; port MCA_CLKOUT32K
MCA_IO9: U7.AG29(MCA_IO9) ; port MCA_IO9
MCA_IO10: U7.AF29(MCA_IO10) ; port MCA_IO10
MCA_IO11: U7.AM26(MCA_IO11) ; port MCA_IO11
MCA_IO12: U7.AM25(MCA_IO12) ; port MCA_IO12
MCA_IO13: U7.AL22(MCA_IO13) ; port MCA_IO13
MCA_IO14: U7.AL26(MCA_IO14) ; port MCA_IO14
MCA_IO15: U7.AL25(MCA_IO15) ; port MCA_IO15
MCA_IO16: U7.AL24(MCA_IO16) ; port MCA_IO16
MCA_IO17: U7.AL23(MCA_IO17) ; port MCA_IO17
MCA_IO18: U7.AM23(MCA_IO18) ; port MCA_IO18
MCA_UART_CTS: U7.AN23(MCA_IO3) ; port MCA_UART_CTS
MCA_UART_RTS: U7.AL27(MCA_IO4) ; port MCA_UART_RTS
MCA_UART_RX: U7.AN22(MCA_IO2) ; port MCA_UART_RX
MCA_UART_TX: U7.AN21(MCA_IO1) ; port MCA_UART_TX
MCA_VIN_DET: U7.AM27(MCA_VIN_DET) ; port MCA_VIN_DET
MCA_VREF_OUT: U7.AM24(MCA_VREF_OUT) ; port MCA_VREF_OUT
POR_B: U7.AH10(POR_B) ; port POR_B
PWR_ON: U7.AJ12(PWR_ON) ; port PWR_ON
SD2_VSELECT: U7.AH13(SD_VSELECT) ; port SD2_VSELECT
SW_EN: U7.F2(SW_EN) ; port SW_EN
SWD_CLK/PWR_IO: U7.AN24(SWD_CLK/PWR_IO) ; port SWD_CLK/PWR_IO
SWD_DIO: U7.AN26(SWD_DIO/MCA_IO0) ; port SWD_DIO
SYS_RESET: U7.AN25(SYS_RESET) ; port SYS_RESET
NetJ6_2: J6.2 R33.2 R34.1 R35.1
NetJ9_2: J9.2 U7.AL20(RESERVED)
NetR36_2: R36.2 U7.AJ10(NC)
NetR37_2: R37.2 U7.AH7(NC)
NetR38_2: R38.2 U7.F20(MUX_3V3_1V8)
NetR39_2: R39.2 R40.2 U7.N1(NVCC_SD2)
NetR41_2: R41.2 U7.E14(SWIN)
NetR42_2: R42.2 U7.AG17(SWOUT)
NetR45_2: R45.2 U7.E5(1V8)
NetTP1_1: TP1.1 U7.AJ11(PMIC_STANDBY)
NetTP2_1: TP2.1 U7.AH6(RESERVED)
NetTP3_1: TP3.1 U7.AH12(RESERVED)
NetTP4_1: TP4.1 U7.AM19(RESERVED)
NetTP5_1: TP5.1 U7.AL19(RESERVED)

Not connected (* = marked no-connect by the designer): U7 AA29(NC)* AB29(NC)* AC29(NC)* AD29(NC)* AE29(NC)* AG19(NC)* AG22(NC)* AG24(NC)* AH9(NC)* AH11(NC)* AH18(NC)* AH29(NC)* AJ8(NC)* AJ13(NC)* AJ27(NC)* AJ28(NC)* AJ29(NC)* AK29(NC)* AL28(NC)* AM7(NC)* AM8(NC)* AM9(NC)* AM22(RESERVED)* D15(NC)* E16(NC)* J29(NC)* U1(NC)*

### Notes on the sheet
- For debug only, leave AL20 unconnected

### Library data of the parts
J6-J9 = 1001128: as J3 on sheet 02 - Power, reset
R33 = 1000208: as R16 on sheet 02 - Power, reset
R34 R35 R38 R43 R44 = 1000208: RES 0.0 OHM 1/10W 0603; Part_Type: Resistor; Manufacturer: Panasonic - ECG; Manufacturer_Part_Number: ERJ-3GEY0R00V; Note: 13051103 = Digi No. for GE WDNU; Digi_PN: 13050568; Component_Life_Cycle_State: Reviewed; Area: 2,5; Project: Adjustable Foundation; Voltage: 75V
R36 R37 R39-R42 R45 = 1000076: as R9 on sheet 02 - Power, reset
TP1-TP5 = CAD0011: TEST POINT 30MIL PAD SMT; Component_Life_Cycle_State: Reviewed; Area: 0,58; Project: CLC
U7 = 1002856: ConnectCore for i.MX93 module; Manufacturer: DIGI; Digi_PN: 55002169-01; Component_Life_Cycle_State: Pending

## Sheet 04 - CCIMX93 Digital interfaces.SchDoc: CCIMX93 Digital interfaces
size A3; PageSetup: Record=PageOptions¦CenterHorizontal=True¦CenterVertical=True¦PrintScale=0.70¦XCorrection=1.00¦YCorrection=1.00¦PrintKind=0¦BorderSize=5000000¦LeftOffset=0¦BottomOffset=0¦Orientation=2¦PaperLength=4200¦PaperWidth=2970¦Scale=100¦PaperSource=7¦PrintQuality=600¦MediaType=1¦DitherType=10¦PaperKind=A4¦PrintScaleMode=1; Author: Juan Anzola; SheetNumber: 4; SheetTotal: 20
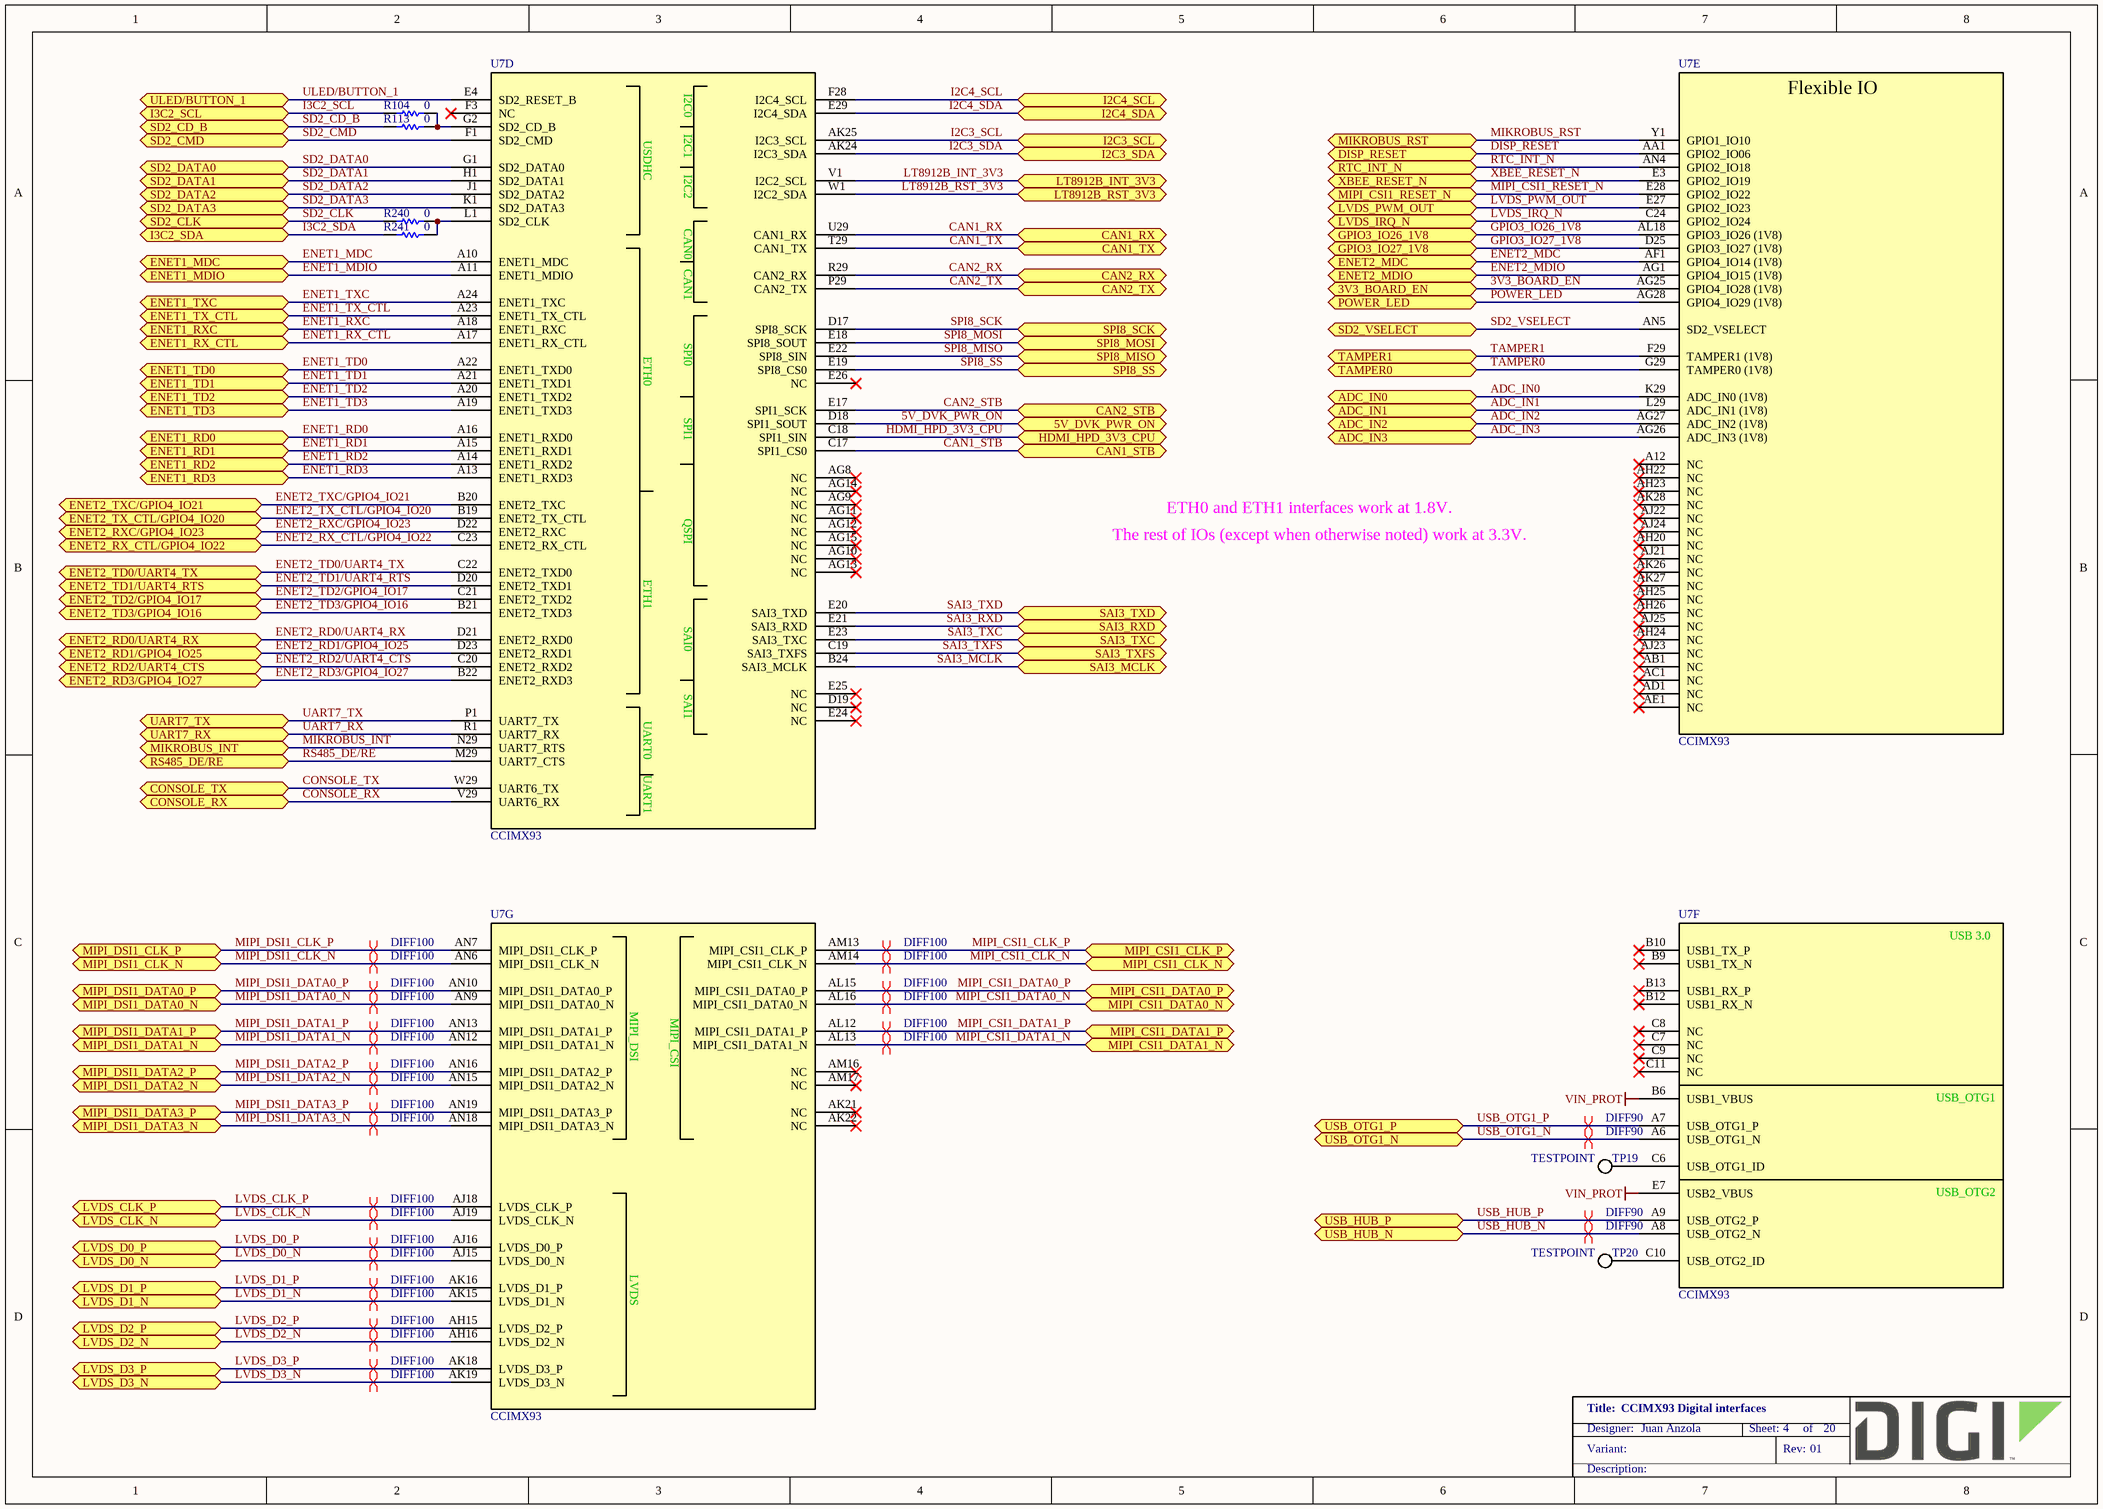
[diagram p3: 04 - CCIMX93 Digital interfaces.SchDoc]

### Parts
R104  0  [RESC1005X40N]
R113  0  [RESC1005X40N]
R240  0  [RESC1005X40N]
R241  0  [RESC1005X40N]
TP19  TESTPOINT  [TP0762]  (no BOM)
TP20  TESTPOINT  [TP0762]  (no BOM)
U7  CCIMX93  [CC93_DVK]  (parts D,E,F,G of 10)

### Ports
3V3_BOARD_EN (bidir), 5V_DVK_PWR_ON (bidir), ADC_IN0 (bidir), ADC_IN1 (bidir), ADC_IN2 (bidir), ADC_IN3 (bidir), CAN1_RX (bidir), CAN1_STB (bidir), CAN1_TX (bidir), CAN2_RX (bidir), CAN2_STB (bidir), CAN2_TX (bidir), CONSOLE_RX (bidir), CONSOLE_TX (bidir), DISP_RESET (bidir), ENET1_MDC (bidir), ENET1_MDIO (bidir), ENET1_RD0 (bidir), ENET1_RD1 (bidir), ENET1_RD2 (bidir), ENET1_RD3 (bidir), ENET1_RX_CTL (bidir), ENET1_RXC (bidir), ENET1_TD0 (bidir), ENET1_TD1 (bidir), ENET1_TD2 (bidir), ENET1_TD3 (bidir), ENET1_TX_CTL (bidir), ENET1_TXC (bidir), ENET2_MDC (bidir), ENET2_MDIO (bidir), ENET2_RD0/UART4_RX (bidir), ENET2_RD1/GPIO4_IO25 (bidir), ENET2_RD2/UART4_CTS (bidir), ENET2_RD3/GPIO4_IO27 (bidir), ENET2_RX_CTL/GPIO4_IO22 (bidir), ENET2_RXC/GPIO4_IO23 (bidir), ENET2_TD0/UART4_TX (bidir), ENET2_TD1/UART4_RTS (bidir), ENET2_TD2/GPIO4_IO17 (bidir), ENET2_TD3/GPIO4_IO16 (bidir), ENET2_TX_CTL/GPIO4_IO20 (bidir), ENET2_TXC/GPIO4_IO21 (bidir), GPIO3_IO26_1V8 (bidir), GPIO3_IO27_1V8 (bidir), HDMI_HPD_3V3_CPU (bidir), I2C3_SCL (bidir), I2C3_SDA (bidir), I2C4_SCL (bidir), I2C4_SDA (bidir), I3C2_SCL (bidir), I3C2_SDA (bidir), LT8912B_INT_3V3 (bidir), LT8912B_RST_3V3 (bidir), LVDS_CLK_N (bidir), LVDS_CLK_P (bidir), LVDS_D0_N (bidir), LVDS_D0_P (bidir), LVDS_D1_N (bidir), LVDS_D1_P (bidir), LVDS_D2_N (bidir), LVDS_D2_P (bidir), LVDS_D3_N (bidir), LVDS_D3_P (bidir), LVDS_IRQ_N (bidir), LVDS_PWM_OUT (bidir), MIKROBUS_INT (bidir), MIKROBUS_RST (bidir), MIPI_CSI1_CLK_N (bidir), MIPI_CSI1_CLK_P (bidir), MIPI_CSI1_DATA0_N (bidir), MIPI_CSI1_DATA0_P (bidir), MIPI_CSI1_DATA1_N (bidir), MIPI_CSI1_DATA1_P (bidir), MIPI_CSI1_RESET_N (bidir), MIPI_DSI1_CLK_N (bidir), MIPI_DSI1_CLK_P (bidir), MIPI_DSI1_DATA0_N (bidir), MIPI_DSI1_DATA0_P (bidir), MIPI_DSI1_DATA1_N (bidir), MIPI_DSI1_DATA1_P (bidir), MIPI_DSI1_DATA2_N (bidir), MIPI_DSI1_DATA2_P (bidir), MIPI_DSI1_DATA3_N (bidir), MIPI_DSI1_DATA3_P (bidir), POWER_LED (bidir), RS485_DE/RE (bidir), RTC_INT_N (bidir), SAI3_MCLK (bidir), SAI3_RXD (bidir), SAI3_TXC (bidir), SAI3_TXD (bidir), SAI3_TXFS (bidir), SD2_CD_B (bidir), SD2_CLK (bidir), SD2_CMD (bidir), SD2_DATA0 (bidir), SD2_DATA1 (bidir), SD2_DATA2 (bidir), SD2_DATA3 (bidir), SD2_VSELECT (bidir), SPI8_MISO (bidir), SPI8_MOSI (bidir), SPI8_SCK (bidir), SPI8_SS (bidir), TAMPER0 (bidir), TAMPER1 (bidir), UART7_RX (bidir), UART7_TX (bidir), ULED/BUTTON_1 (bidir), USB_HUB_N (bidir), USB_HUB_P (bidir), USB_OTG1_N (bidir), USB_OTG1_P (bidir), XBEE_RESET_N (bidir)

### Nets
VIN_PROT: U7.B6(USB1_VBUS) U7.E7(USB2_VBUS)
3V3_BOARD_EN: U7.AG25(GPIO4_IO28_(1V8)) ; port 3V3_BOARD_EN
5V_DVK_PWR_ON: U7.D18(SPI1_SOUT) ; port 5V_DVK_PWR_ON
ADC_IN0: U7.K29(ADC_IN0_(1V8)) ; port ADC_IN0
ADC_IN1: U7.L29(ADC_IN1_(1V8)) ; port ADC_IN1
ADC_IN2: U7.AG27(ADC_IN2_(1V8)) ; port ADC_IN2
ADC_IN3: U7.AG26(ADC_IN3_(1V8)) ; port ADC_IN3
CAN1_RX: U7.U29(CAN1_RX) ; port CAN1_RX
CAN1_STB: U7.C17(SPI1_CS0) ; port CAN1_STB
CAN1_TX: U7.T29(CAN1_TX) ; port CAN1_TX
CAN2_RX: U7.R29(CAN2_RX) ; port CAN2_RX
CAN2_STB: U7.E17(SPI1_SCK) ; port CAN2_STB
CAN2_TX: U7.P29(CAN2_TX) ; port CAN2_TX
CONSOLE_RX: U7.V29(UART6_RX) ; port CONSOLE_RX
CONSOLE_TX: U7.W29(UART6_TX) ; port CONSOLE_TX
DISP_RESET: U7.AA1(GPIO2_IO06) ; port DISP_RESET
ENET1_MDC: U7.A10(ENET1_MDC) ; port ENET1_MDC
ENET1_MDIO: U7.A11(ENET1_MDIO) ; port ENET1_MDIO
ENET1_RD0: U7.A16(ENET1_RXD0) ; port ENET1_RD0
ENET1_RD1: U7.A15(ENET1_RXD1) ; port ENET1_RD1
ENET1_RD2: U7.A14(ENET1_RXD2) ; port ENET1_RD2
ENET1_RD3: U7.A13(ENET1_RXD3) ; port ENET1_RD3
ENET1_RX_CTL: U7.A17(ENET1_RX_CTL) ; port ENET1_RX_CTL
ENET1_RXC: U7.A18(ENET1_RXC) ; port ENET1_RXC
ENET1_TD0: U7.A22(ENET1_TXD0) ; port ENET1_TD0
ENET1_TD1: U7.A21(ENET1_TXD1) ; port ENET1_TD1
ENET1_TD2: U7.A20(ENET1_TXD2) ; port ENET1_TD2
ENET1_TD3: U7.A19(ENET1_TXD3) ; port ENET1_TD3
ENET1_TX_CTL: U7.A23(ENET1_TX_CTL) ; port ENET1_TX_CTL
ENET1_TXC: U7.A24(ENET1_TXC) ; port ENET1_TXC
ENET2_MDC: U7.AF1(GPIO4_IO14_(1V8)) ; port ENET2_MDC
ENET2_MDIO: U7.AG1(GPIO4_IO15_(1V8)) ; port ENET2_MDIO
ENET2_RD0/UART4_RX: U7.D21(ENET2_RXD0) ; port ENET2_RD0/UART4_RX
ENET2_RD1/GPIO4_IO25: U7.D23(ENET2_RXD1) ; port ENET2_RD1/GPIO4_IO25
ENET2_RD2/UART4_CTS: U7.C20(ENET2_RXD2) ; port ENET2_RD2/UART4_CTS
ENET2_RD3/GPIO4_IO27: U7.B22(ENET2_RXD3) ; port ENET2_RD3/GPIO4_IO27
ENET2_RX_CTL/GPIO4_IO22: U7.C23(ENET2_RX_CTL) ; port ENET2_RX_CTL/GPIO4_IO22
ENET2_RXC/GPIO4_IO23: U7.D22(ENET2_RXC) ; port ENET2_RXC/GPIO4_IO23
ENET2_TD0/UART4_TX: U7.C22(ENET2_TXD0) ; port ENET2_TD0/UART4_TX
ENET2_TD1/UART4_RTS: U7.D20(ENET2_TXD1) ; port ENET2_TD1/UART4_RTS
ENET2_TD2/GPIO4_IO17: U7.C21(ENET2_TXD2) ; port ENET2_TD2/GPIO4_IO17
ENET2_TD3/GPIO4_IO16: U7.B21(ENET2_TXD3) ; port ENET2_TD3/GPIO4_IO16
ENET2_TX_CTL/GPIO4_IO20: U7.B19(ENET2_TX_CTL) ; port ENET2_TX_CTL/GPIO4_IO20
ENET2_TXC/GPIO4_IO21: U7.B20(ENET2_TXC) ; port ENET2_TXC/GPIO4_IO21
GPIO3_IO26_1V8: U7.AL18(GPIO3_IO26_(1V8)) ; port GPIO3_IO26_1V8
GPIO3_IO27_1V8: U7.D25(GPIO3_IO27_(1V8)) ; port GPIO3_IO27_1V8
HDMI_HPD_3V3_CPU: U7.C18(SPI1_SIN) ; port HDMI_HPD_3V3_CPU
I2C3_SCL: U7.AK25(I2C3_SCL) ; port I2C3_SCL
I2C3_SDA: U7.AK24(I2C3_SDA) ; port I2C3_SDA
I2C4_SCL: U7.F28(I2C4_SCL) ; port I2C4_SCL
I2C4_SDA: U7.E29(I2C4_SDA) ; port I2C4_SDA
I3C2_SCL: R104.1 ; port I3C2_SCL
I3C2_SDA: R241.1 ; port I3C2_SDA
LT8912B_INT_3V3: U7.V1(I2C2_SCL) ; port LT8912B_INT_3V3
LT8912B_RST_3V3: U7.W1(I2C2_SDA) ; port LT8912B_RST_3V3
LVDS_CLK_N: U7.AJ19(LVDS_CLK_N) ; port LVDS_CLK_N
LVDS_CLK_P: U7.AJ18(LVDS_CLK_P) ; port LVDS_CLK_P
LVDS_D0_N: U7.AJ15(LVDS_D0_N) ; port LVDS_D0_N
LVDS_D0_P: U7.AJ16(LVDS_D0_P) ; port LVDS_D0_P
LVDS_D1_N: U7.AK15(LVDS_D1_N) ; port LVDS_D1_N
LVDS_D1_P: U7.AK16(LVDS_D1_P) ; port LVDS_D1_P
LVDS_D2_N: U7.AH16(LVDS_D2_N) ; port LVDS_D2_N
LVDS_D2_P: U7.AH15(LVDS_D2_P) ; port LVDS_D2_P
LVDS_D3_N: U7.AK19(LVDS_D3_N) ; port LVDS_D3_N
LVDS_D3_P: U7.AK18(LVDS_D3_P) ; port LVDS_D3_P
LVDS_IRQ_N: U7.C24(GPIO2_IO24) ; port LVDS_IRQ_N
LVDS_PWM_OUT: U7.E27(GPIO2_IO23) ; port LVDS_PWM_OUT
MIKROBUS_INT: U7.N29(UART7_RTS) ; port MIKROBUS_INT
MIKROBUS_RST: U7.Y1(GPIO1_IO10) ; port MIKROBUS_RST
MIPI_CSI1_CLK_N: U7.AM14(MIPI_CSI1_CLK_N) ; port MIPI_CSI1_CLK_N
MIPI_CSI1_CLK_P: U7.AM13(MIPI_CSI1_CLK_P) ; port MIPI_CSI1_CLK_P
MIPI_CSI1_DATA0_N: U7.AL16(MIPI_CSI1_DATA0_N) ; port MIPI_CSI1_DATA0_N
MIPI_CSI1_DATA0_P: U7.AL15(MIPI_CSI1_DATA0_P) ; port MIPI_CSI1_DATA0_P
MIPI_CSI1_DATA1_N: U7.AL13(MIPI_CSI1_DATA1_N) ; port MIPI_CSI1_DATA1_N
MIPI_CSI1_DATA1_P: U7.AL12(MIPI_CSI1_DATA1_P) ; port MIPI_CSI1_DATA1_P
MIPI_CSI1_RESET_N: U7.E28(GPIO2_IO22) ; port MIPI_CSI1_RESET_N
MIPI_DSI1_CLK_N: U7.AN6(MIPI_DSI1_CLK_N) ; port MIPI_DSI1_CLK_N
MIPI_DSI1_CLK_P: U7.AN7(MIPI_DSI1_CLK_P) ; port MIPI_DSI1_CLK_P
MIPI_DSI1_DATA0_N: U7.AN9(MIPI_DSI1_DATA0_N) ; port MIPI_DSI1_DATA0_N
MIPI_DSI1_DATA0_P: U7.AN10(MIPI_DSI1_DATA0_P) ; port MIPI_DSI1_DATA0_P
MIPI_DSI1_DATA1_N: U7.AN12(MIPI_DSI1_DATA1_N) ; port MIPI_DSI1_DATA1_N
MIPI_DSI1_DATA1_P: U7.AN13(MIPI_DSI1_DATA1_P) ; port MIPI_DSI1_DATA1_P
MIPI_DSI1_DATA2_N: U7.AN15(MIPI_DSI1_DATA2_N) ; port MIPI_DSI1_DATA2_N
MIPI_DSI1_DATA2_P: U7.AN16(MIPI_DSI1_DATA2_P) ; port MIPI_DSI1_DATA2_P
MIPI_DSI1_DATA3_N: U7.AN18(MIPI_DSI1_DATA3_N) ; port MIPI_DSI1_DATA3_N
MIPI_DSI1_DATA3_P: U7.AN19(MIPI_DSI1_DATA3_P) ; port MIPI_DSI1_DATA3_P
POWER_LED: U7.AG28(GPIO4_IO29_(1V8)) ; port POWER_LED
RS485_DE/RE: U7.M29(UART7_CTS) ; port RS485_DE/RE
RTC_INT_N: U7.AN4(GPIO2_IO18) ; port RTC_INT_N
SAI3_MCLK: U7.B24(SAI3_MCLK) ; port SAI3_MCLK
SAI3_RXD: U7.E21(SAI3_RXD) ; port SAI3_RXD
SAI3_TXC: U7.E23(SAI3_TXC) ; port SAI3_TXC
SAI3_TXD: U7.E20(SAI3_TXD) ; port SAI3_TXD
SAI3_TXFS: U7.C19(SAI3_TXFS) ; port SAI3_TXFS
SD2_CD_B: R113.1 ; port SD2_CD_B
SD2_CLK: R240.1 ; port SD2_CLK
SD2_CMD: U7.F1(SD2_CMD) ; port SD2_CMD
SD2_DATA0: U7.G1(SD2_DATA0) ; port SD2_DATA0
SD2_DATA1: U7.H1(SD2_DATA1) ; port SD2_DATA1
SD2_DATA2: U7.J1(SD2_DATA2) ; port SD2_DATA2
SD2_DATA3: U7.K1(SD2_DATA3) ; port SD2_DATA3
SD2_VSELECT: U7.AN5(SD2_VSELECT) ; port SD2_VSELECT
SPI8_MISO: U7.E22(SPI8_SIN) ; port SPI8_MISO
SPI8_MOSI: U7.E18(SPI8_SOUT) ; port SPI8_MOSI
SPI8_SCK: U7.D17(SPI8_SCK) ; port SPI8_SCK
SPI8_SS: U7.E19(SPI8_CS0) ; port SPI8_SS
TAMPER0: U7.G29(TAMPER0_(1V8)) ; port TAMPER0
TAMPER1: U7.F29(TAMPER1_(1V8)) ; port TAMPER1
UART7_RX: U7.R1(UART7_RX) ; port UART7_RX
UART7_TX: U7.P1(UART7_TX) ; port UART7_TX
ULED/BUTTON_1: U7.E4(SD2_RESET_B) ; port ULED/BUTTON_1
USB_HUB_N: U7.A8(USB_OTG2_N) ; port USB_HUB_N
USB_HUB_P: U7.A9(USB_OTG2_P) ; port USB_HUB_P
USB_OTG1_N: U7.A6(USB_OTG1_N) ; port USB_OTG1_N
USB_OTG1_P: U7.A7(USB_OTG1_P) ; port USB_OTG1_P
XBEE_RESET_N: U7.E3(GPIO2_IO19) ; port XBEE_RESET_N
NetR104_2: R104.2 R113.2 U7.G2(SD2_CD_B)
NetR240_2: R240.2 R241.2 U7.L1(SD2_CLK)
NetTP19_1: TP19.1 U7.C6(USB_OTG1_ID)
NetTP20_1: TP20.1 U7.C10(USB_OTG2_ID)

Not connected (* = marked no-connect by the designer): U7 A12(NC)* AB1(NC)* AC1(NC)* AD1(NC)* AE1(NC)* AG8(NC)* AG9(NC)* AG10(NC)* AG11(NC)* AG12(NC)* AG13(NC)* AG14(NC)* AG15(NC)* AH20(NC)* AH22(NC)* AH23(NC)* AH24(NC)* AH25(NC)* AH26(NC)* AJ21(NC)* AJ22(NC)* AJ23(NC)* AJ24(NC)* AJ25(NC)* AK21(NC)* AK22(NC)* AK26(NC)* AK27(NC)* AK28(NC)* AM16(NC)* AM17(NC)* B9(USB1_TX_N)* B10(USB1_TX_P)* B12(USB1_RX_N)* B13(USB1_RX_P)* C7(NC)* C8(NC)* C9(NC)* C11(NC)* D19(NC)* E24(NC)* E25(NC)* E26(NC)* F3(NC)*

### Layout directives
differential pair; net class DIFF100; differential pair class DIFF100: LVDS_CLK_N, LVDS_CLK_P, LVDS_D0_N, LVDS_D0_P, LVDS_D1_N, LVDS_D1_P, LVDS_D2_N, LVDS_D2_P, LVDS_D3_N, LVDS_D3_P, MIPI_CSI1_CLK_N, MIPI_CSI1_CLK_P, MIPI_CSI1_DATA0_N, MIPI_CSI1_DATA0_P, MIPI_CSI1_DATA1_N, MIPI_CSI1_DATA1_P, MIPI_DSI1_CLK_N, MIPI_DSI1_CLK_P, MIPI_DSI1_DATA0_N, MIPI_DSI1_DATA0_P, MIPI_DSI1_DATA1_N, MIPI_DSI1_DATA1_P, MIPI_DSI1_DATA2_N, MIPI_DSI1_DATA2_P, MIPI_DSI1_DATA3_N, MIPI_DSI1_DATA3_P
differential pair; net class DIFF90; differential pair class DIFF90: USB_HUB_N, USB_HUB_P, USB_OTG1_N, USB_OTG1_P

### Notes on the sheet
- ETH0 and ETH1 interfaces work at 1.8V.
- The rest of IOs (except when otherwise noted) work at 3.3V.

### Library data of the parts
R104 R113 R240 R241 = 1000076: as R9 on sheet 02 - Power, reset
TP19 TP20 = CAD0011: as TP1 on sheet 03 - CCIMX93 Power, Control, MCA
U7 = 1002856: as U7 on sheet 03 - CCIMX93 Power, Control, MCA

## Sheet 05 - CCIMX93 RF.SchDoc: CCIMX93 RF
size A3; PageSetup: Record=PageOptions¦CenterHorizontal=True¦CenterVertical=True¦PrintScale=0.70¦XCorrection=1.00¦YCorrection=1.00¦PrintKind=0¦BorderSize=5000000¦LeftOffset=0¦BottomOffset=0¦Orientation=2¦PaperLength=4200¦PaperWidth=2970¦Scale=100¦PaperSource=7¦PrintQuality=600¦MediaType=1¦DitherType=10¦PaperKind=A4¦PrintScaleMode=1; Author: Juan Anzola; SheetNumber: 5; SheetTotal: 20
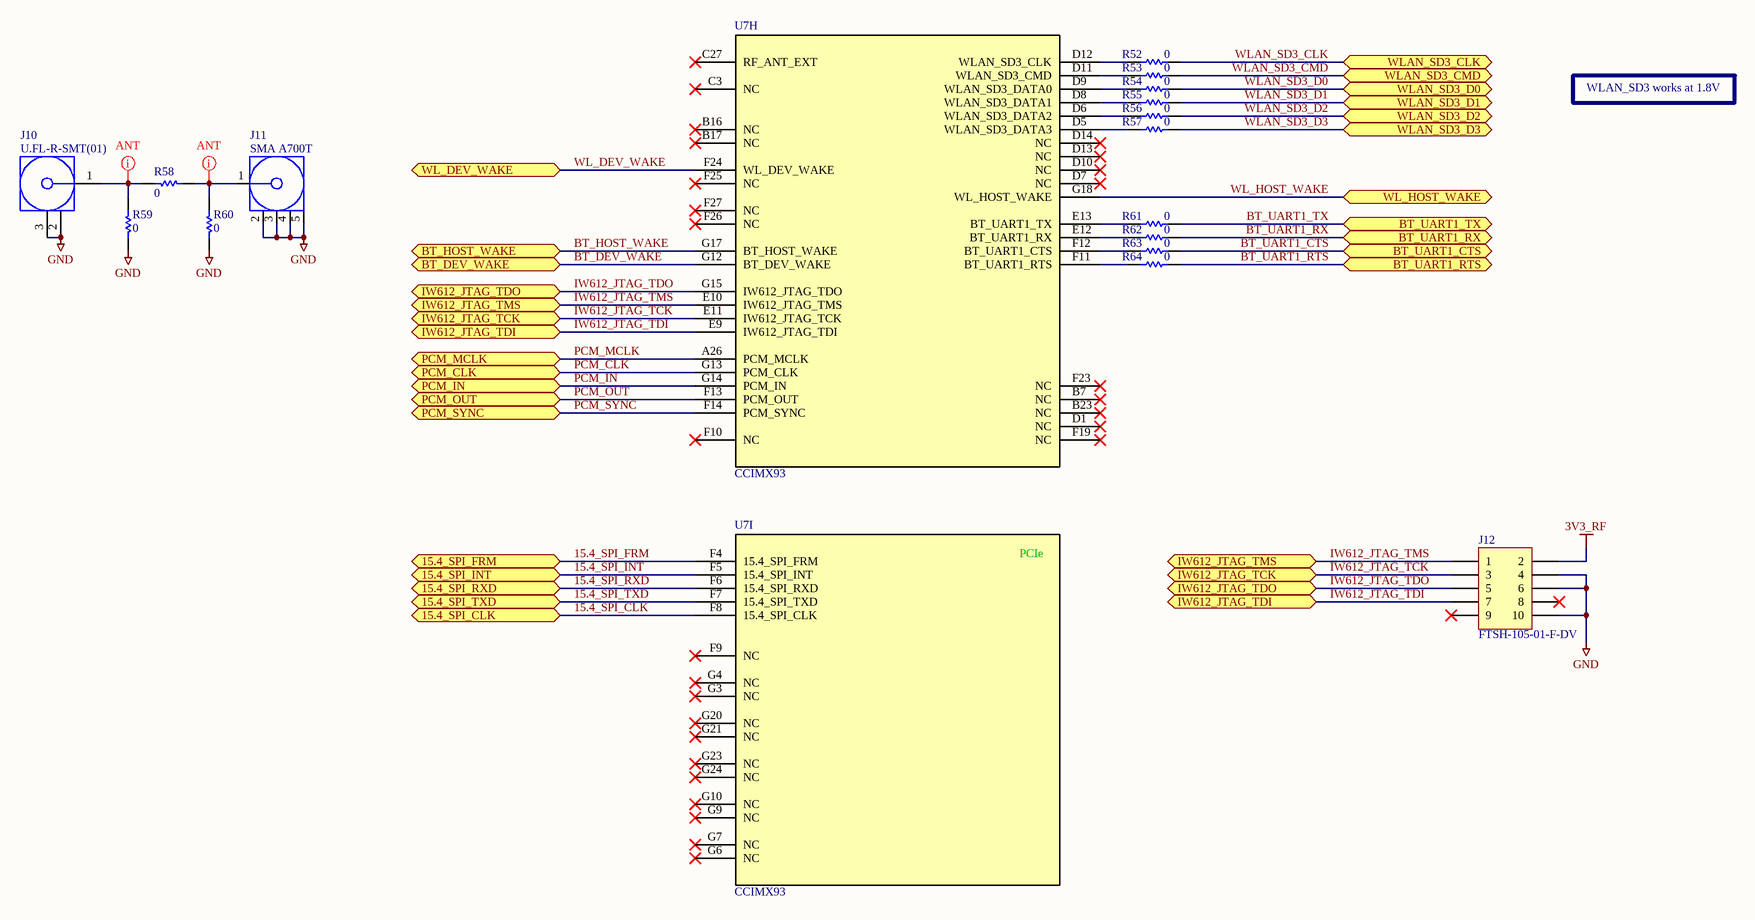
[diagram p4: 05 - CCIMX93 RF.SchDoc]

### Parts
J10  U.FL-R-SMT(01)  [HIROSE_U.FL-R-SMT(01)]
J11  SMA A700T  [BOBBINTRON_SMA A700T]
J12  FTSH-105-01-F-DV  [SAMTEC_FTSH-105-01-F-DV]
R52  0  [RESC1005X40N]
R53  0  [RESC1005X40N]
R54  0  [RESC1005X40N]
R55  0  [RESC1005X40N]
R56  0  [RESC1005X40N]
R57  0  [RESC1005X40N]
R58  0  [RESC1005X40N]
R59  0  [RESC1005X40N]
R60  0  [RESC1005X40N]
R61  0  [RESC1005X40N]
R62  0  [RESC1005X40N]
R63  0  [RESC1005X40N]
R64  0  [RESC1005X40N]
U7  CCIMX93  [CC93_DVK]  (parts H,I of 10)

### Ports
15.4_SPI_CLK (bidir), 15.4_SPI_FRM (bidir), 15.4_SPI_INT (bidir), 15.4_SPI_RXD (bidir), 15.4_SPI_TXD (bidir), BT_DEV_WAKE (bidir), BT_HOST_WAKE (bidir), BT_UART1_CTS (bidir), BT_UART1_RTS (bidir), BT_UART1_RX (bidir), BT_UART1_TX (bidir), IW612_JTAG_TCK (bidir), IW612_JTAG_TDI (bidir), IW612_JTAG_TDO (bidir), IW612_JTAG_TMS (bidir), PCM_CLK (bidir), PCM_IN (bidir), PCM_MCLK (bidir), PCM_OUT (bidir), PCM_SYNC (bidir), WL_DEV_WAKE (bidir), WL_HOST_WAKE (bidir), WLAN_SD3_CLK (bidir), WLAN_SD3_CMD (bidir), WLAN_SD3_D0 (bidir), WLAN_SD3_D1 (bidir), WLAN_SD3_D2 (bidir), WLAN_SD3_D3 (bidir)

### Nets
3V3_RF: J12.2
GND: J10.2(GND) J10.3(GND) J11.2(GND) J11.3(GND) J11.4(GND) J11.5(GND) J12.4 J12.6 J12.10 R59.1 R60.1
15.4_SPI_CLK: U7.F8(15.4_SPI_CLK) ; port 15.4_SPI_CLK
15.4_SPI_FRM: U7.F4(15.4_SPI_FRM) ; port 15.4_SPI_FRM
15.4_SPI_INT: U7.F5(15.4_SPI_INT) ; port 15.4_SPI_INT
15.4_SPI_RXD: U7.F6(15.4_SPI_RXD) ; port 15.4_SPI_RXD
15.4_SPI_TXD: U7.F7(15.4_SPI_TXD) ; port 15.4_SPI_TXD
BT_DEV_WAKE: U7.G12(BT_DEV_WAKE) ; port BT_DEV_WAKE
BT_HOST_WAKE: U7.G17(BT_HOST_WAKE) ; port BT_HOST_WAKE
BT_UART1_CTS: R63.2 ; port BT_UART1_CTS
BT_UART1_RTS: R64.2 ; port BT_UART1_RTS
BT_UART1_RX: R62.2 ; port BT_UART1_RX
BT_UART1_TX: R61.2 ; port BT_UART1_TX
IW612_JTAG_TCK: J12.3 U7.E11(IW612_JTAG_TCK) ; port IW612_JTAG_TCK
IW612_JTAG_TDI: J12.7 U7.E9(IW612_JTAG_TDI) ; port IW612_JTAG_TDI
IW612_JTAG_TDO: J12.5 U7.G15(IW612_JTAG_TDO) ; port IW612_JTAG_TDO
IW612_JTAG_TMS: J12.1 U7.E10(IW612_JTAG_TMS) ; port IW612_JTAG_TMS
PCM_CLK: U7.G13(PCM_CLK) ; port PCM_CLK
PCM_IN: U7.G14(PCM_IN) ; port PCM_IN
PCM_MCLK: U7.A26(PCM_MCLK) ; port PCM_MCLK
PCM_OUT: U7.F13(PCM_OUT) ; port PCM_OUT
PCM_SYNC: U7.F14(PCM_SYNC) ; port PCM_SYNC
WL_DEV_WAKE: U7.F24(WL_DEV_WAKE) ; port WL_DEV_WAKE
WL_HOST_WAKE: U7.G18(WL_HOST_WAKE) ; port WL_HOST_WAKE
WLAN_SD3_CLK: R52.2 ; port WLAN_SD3_CLK
WLAN_SD3_CMD: R53.2 ; port WLAN_SD3_CMD
WLAN_SD3_D0: R54.2 ; port WLAN_SD3_D0
WLAN_SD3_D1: R55.2 ; port WLAN_SD3_D1
WLAN_SD3_D2: R56.2 ; port WLAN_SD3_D2
WLAN_SD3_D3: R57.2 ; port WLAN_SD3_D3
NetJ10_1: J10.1(Signal) R58.2 R59.2
NetJ11_1: J11.1(Signal) R58.1 R60.2
NetR52_1: R52.1 U7.D12(WLAN_SD3_CLK)
NetR53_1: R53.1 U7.D11(WLAN_SD3_CMD)
NetR54_1: R54.1 U7.D9(WLAN_SD3_DATA0)
NetR55_1: R55.1 U7.D8(WLAN_SD3_DATA1)
NetR56_1: R56.1 U7.D6(WLAN_SD3_DATA2)
NetR57_1: R57.1 U7.D5(WLAN_SD3_DATA3)
NetR61_1: R61.1 U7.E13(BT_UART1_TX)
NetR62_1: R62.1 U7.E12(BT_UART1_RX)
NetR63_1: R63.1 U7.F12(BT_UART1_CTS)
NetR64_1: R64.1 U7.F11(BT_UART1_RTS)

Not connected (* = marked no-connect by the designer): J12 8* 9*; U7 B7(NC)* B16(NC)* B17(NC)* B23(NC)* C3(NC)* C27(RF_ANT_EXT)* D1(NC)* D7(NC)* D10(NC)* D13(NC)* D14(NC)* F9(NC)* F10(NC)* F19(NC)* F23(NC)* F25(NC)* F26(NC)* F27(NC)* G3(NC)* G4(NC)* G6(NC)* G7(NC)* G9(NC)* G10(NC)* G20(NC)* G21(NC)* G23(NC)* G24(NC)*

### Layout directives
net class ANT: NetJ10_1, NetJ11_1

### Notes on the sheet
- WLAN_SD3 works at 1.8V

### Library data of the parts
J10 = 1000027: RF Connectors U.FL RECEPTACLE SMT GLD M CONTACT; Manufacturer: Hirose; Digi_PN: 18000684; Component_Life_Cycle_State: Proven; Area: 14,4
J11 = 1002720: CONN SMA JACK R/A 50 OHM L15.1MM PCB TH; Part_Type: Connector; Manufacturer: Bobbintron Electrical Corp; Digi_PN: MA02979; Component_Life_Cycle_State: Reviewed; Area: 121,68
J12 = 1000034: CONN HEADER 10POS DUAL .05" SMD; Part_Type: Connector; Manufacturer: Samtec; Note: 18000715 = Digi No. for GE WDNU; Digi_PN: 18000539; Component_Life_Cycle_State: Proven; Area: 43,55
R52-R57 R61-R64 = 1000076: as R2 on sheet 02 - Power, reset
R58-R60 = 1000076: RES 0.0 OHM 1/10W 0402 SMD; Part_Type: Resistor; Manufacturer: Panasonic - ECG; Manufacturer_Part_Number: ERJ-2GE0R00X; Digi_PN: 13050387; Component_Life_Cycle_State: Proven; Area: 0,95; Project: Adjustable Foundation; Power_WV_SRF: 10
U7 = 1002856: as U7 on sheet 03 - CCIMX93 Power, Control, MCA

## Sheet 06 - Shared interfaces lines selection.SchDoc: Shared interfaces lines selection
size A3; PageSetup: Record=PageOptions¦CenterHorizontal=True¦CenterVertical=True¦PrintScale=0.70¦XCorrection=1.00¦YCorrection=1.00¦PrintKind=0¦BorderSize=5000000¦LeftOffset=0¦BottomOffset=0¦Orientation=2¦PaperLength=4200¦PaperWidth=2970¦Scale=100¦PaperSource=7¦PrintQuality=600¦MediaType=1¦DitherType=10¦PaperKind=A4¦PrintScaleMode=1; Author: Juan Anzola; SheetNumber: 6; SheetTotal: 20
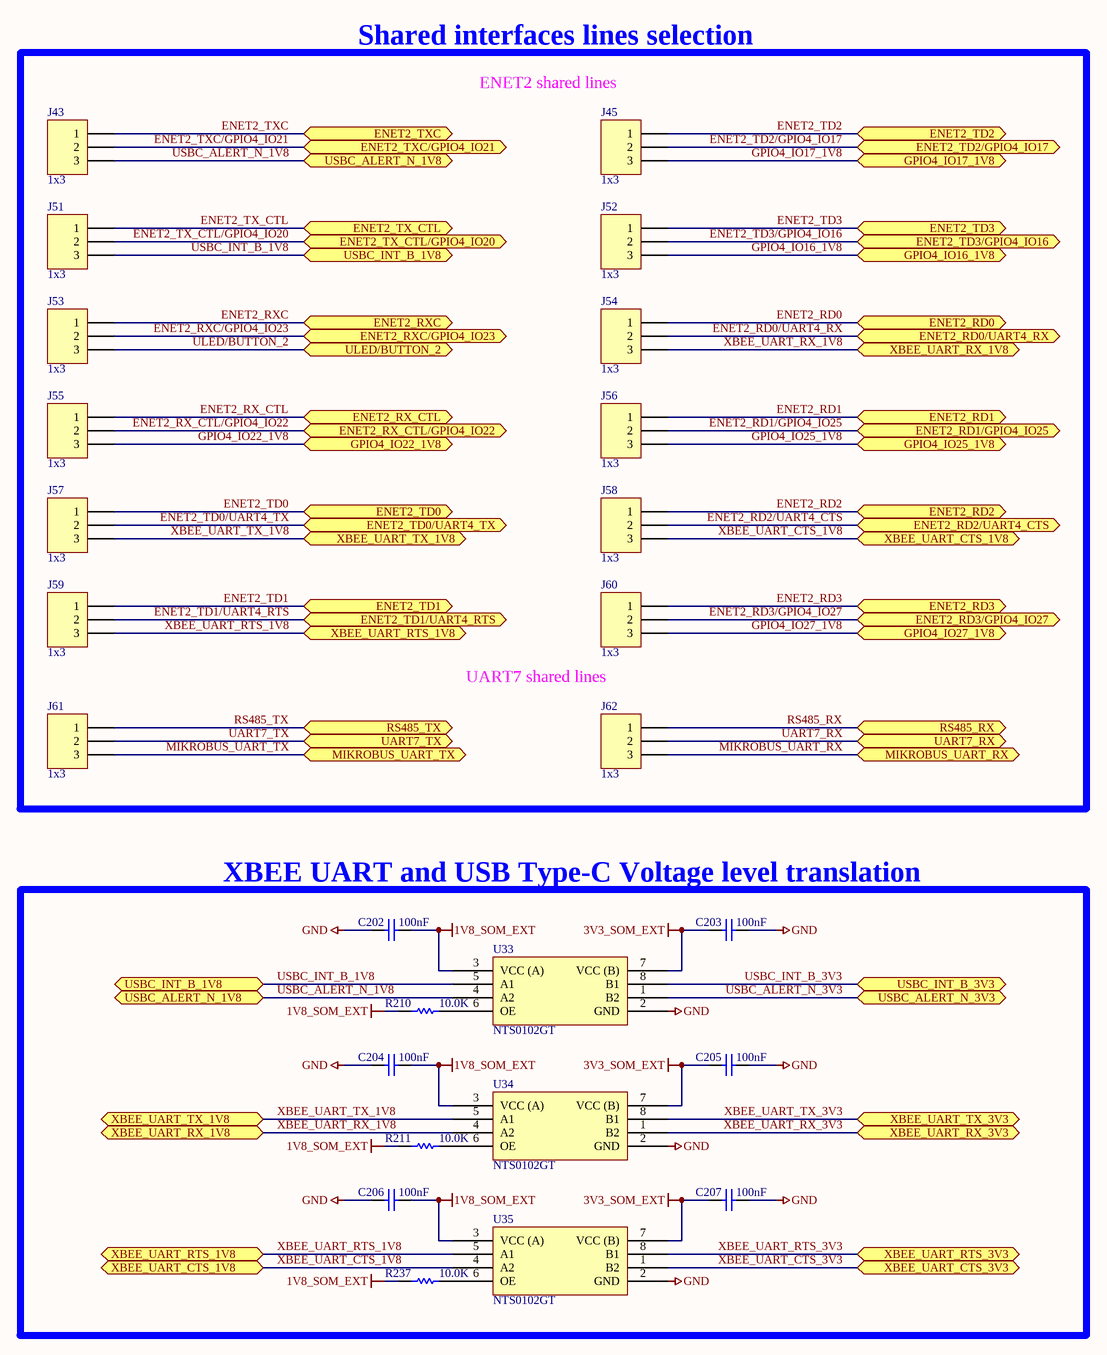
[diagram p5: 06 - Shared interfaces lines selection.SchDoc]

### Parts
C202  100nF  [CAPC1005X55N]
C203  100nF  [CAPC1005X55N]
C204  100nF  [CAPC1005X55N]
C205  100nF  [CAPC1005X55N]
C206  100nF  [CAPC1005X55N]
C207  100nF  [CAPC1005X55N]
J43  1x3  [SAMTEC_TSW-103-07-G-S]
J45  1x3  [SAMTEC_TSW-103-07-G-S]
J51  1x3  [SAMTEC_TSW-103-07-G-S]
J52  1x3  [SAMTEC_TSW-103-07-G-S]
J53  1x3  [SAMTEC_TSW-103-07-G-S]
J54  1x3  [SAMTEC_TSW-103-07-G-S]
J55  1x3  [SAMTEC_TSW-103-07-G-S]
J56  1x3  [SAMTEC_TSW-103-07-G-S]
J57  1x3  [SAMTEC_TSW-103-07-G-S]
J58  1x3  [SAMTEC_TSW-103-07-G-S]
J59  1x3  [SAMTEC_TSW-103-07-G-S]
J60  1x3  [SAMTEC_TSW-103-07-G-S]
J61  1x3  [SAMTEC_TSW-103-07-G-S]
J62  1x3  [SAMTEC_TSW-103-07-G-S]
R210  10.0K  [RESC1005X40N]
R211  10.0K  [RESC1005X40N]
R237  10.0K  [RESC1005X40N]
U33  NTS0102GT  [PSON50P195X100X50-8N]
U34  NTS0102GT  [PSON50P195X100X50-8N]
U35  NTS0102GT  [PSON50P195X100X50-8N]

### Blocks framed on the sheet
Shared interfaces lines selection: J43 J45 J51-J62
XBEE UART and USB Type-C Voltage level translation: C202-C207 R210 R211 R237 U33-U35

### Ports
ENET2_RD0 (bidir), ENET2_RD0/UART4_RX (bidir), ENET2_RD1 (bidir), ENET2_RD1/GPIO4_IO25 (bidir), ENET2_RD2 (bidir), ENET2_RD2/UART4_CTS (bidir), ENET2_RD3 (bidir), ENET2_RD3/GPIO4_IO27 (bidir), ENET2_RX_CTL (bidir), ENET2_RX_CTL/GPIO4_IO22 (bidir), ENET2_RXC (bidir), ENET2_RXC/GPIO4_IO23 (bidir), ENET2_TD0 (bidir), ENET2_TD0/UART4_TX (bidir), ENET2_TD1 (bidir), ENET2_TD1/UART4_RTS (bidir), ENET2_TD2 (bidir), ENET2_TD2/GPIO4_IO17 (bidir), ENET2_TD3 (bidir), ENET2_TD3/GPIO4_IO16 (bidir), ENET2_TX_CTL (bidir), ENET2_TX_CTL/GPIO4_IO20 (bidir), ENET2_TXC (bidir), ENET2_TXC/GPIO4_IO21 (bidir), GPIO4_IO16_1V8 (bidir), GPIO4_IO17_1V8 (bidir), GPIO4_IO22_1V8 (bidir), GPIO4_IO25_1V8 (bidir), GPIO4_IO27_1V8 (bidir), MIKROBUS_UART_RX (bidir), MIKROBUS_UART_TX (bidir), RS485_RX (bidir), RS485_TX (bidir), UART7_RX (bidir), UART7_TX (bidir), ULED/BUTTON_2 (bidir), USBC_ALERT_N_1V8 (bidir), USBC_ALERT_N_3V3 (bidir), USBC_INT_B_1V8 (bidir), USBC_INT_B_3V3 (bidir), XBEE_UART_CTS_1V8 (bidir), XBEE_UART_CTS_3V3 (bidir), XBEE_UART_RTS_1V8 (bidir), XBEE_UART_RTS_3V3 (bidir), XBEE_UART_RX_1V8 (bidir), XBEE_UART_RX_3V3 (bidir), XBEE_UART_TX_1V8 (bidir), XBEE_UART_TX_3V3 (bidir)

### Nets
1V8_SOM_EXT: C202.2 C204.2 C206.2 R210.1 R211.1 R237.1 U33.3(VCC_(A)) U34.3(VCC_(A)) U35.3(VCC_(A))
3V3_SOM_EXT: C203.1 C205.1 C207.1 U33.7(VCC_(B)) U34.7(VCC_(B)) U35.7(VCC_(B))
GND: C202.1 C203.2 C204.1 C205.2 C206.1 C207.2 U33.2(GND) U34.2(GND) U35.2(GND)
ENET2_RD0: J54.1 ; port ENET2_RD0
ENET2_RD0/UART4_RX: J54.2 ; port ENET2_RD0/UART4_RX
ENET2_RD1: J56.1 ; port ENET2_RD1
ENET2_RD1/GPIO4_IO25: J56.2 ; port ENET2_RD1/GPIO4_IO25
ENET2_RD2: J58.1 ; port ENET2_RD2
ENET2_RD2/UART4_CTS: J58.2 ; port ENET2_RD2/UART4_CTS
ENET2_RD3: J60.1 ; port ENET2_RD3
ENET2_RD3/GPIO4_IO27: J60.2 ; port ENET2_RD3/GPIO4_IO27
ENET2_RX_CTL: J55.1 ; port ENET2_RX_CTL
ENET2_RX_CTL/GPIO4_IO22: J55.2 ; port ENET2_RX_CTL/GPIO4_IO22
ENET2_RXC: J53.1 ; port ENET2_RXC
ENET2_RXC/GPIO4_IO23: J53.2 ; port ENET2_RXC/GPIO4_IO23
ENET2_TD0: J57.1 ; port ENET2_TD0
ENET2_TD0/UART4_TX: J57.2 ; port ENET2_TD0/UART4_TX
ENET2_TD1: J59.1 ; port ENET2_TD1
ENET2_TD1/UART4_RTS: J59.2 ; port ENET2_TD1/UART4_RTS
ENET2_TD2: J45.1 ; port ENET2_TD2
ENET2_TD2/GPIO4_IO17: J45.2 ; port ENET2_TD2/GPIO4_IO17
ENET2_TD3: J52.1 ; port ENET2_TD3
ENET2_TD3/GPIO4_IO16: J52.2 ; port ENET2_TD3/GPIO4_IO16
ENET2_TX_CTL: J51.1 ; port ENET2_TX_CTL
ENET2_TX_CTL/GPIO4_IO20: J51.2 ; port ENET2_TX_CTL/GPIO4_IO20
ENET2_TXC: J43.1 ; port ENET2_TXC
ENET2_TXC/GPIO4_IO21: J43.2 ; port ENET2_TXC/GPIO4_IO21
GPIO4_IO16_1V8: J52.3 ; port GPIO4_IO16_1V8
GPIO4_IO17_1V8: J45.3 ; port GPIO4_IO17_1V8
GPIO4_IO22_1V8: J55.3 ; port GPIO4_IO22_1V8
GPIO4_IO25_1V8: J56.3 ; port GPIO4_IO25_1V8
GPIO4_IO27_1V8: J60.3 ; port GPIO4_IO27_1V8
MIKROBUS_UART_RX: J62.3 ; port MIKROBUS_UART_RX
MIKROBUS_UART_TX: J61.3 ; port MIKROBUS_UART_TX
RS485_RX: J62.1 ; port RS485_RX
RS485_TX: J61.1 ; port RS485_TX
UART7_RX: J62.2 ; port UART7_RX
UART7_TX: J61.2 ; port UART7_TX
ULED/BUTTON_2: J53.3 ; port ULED/BUTTON_2
USBC_ALERT_N_1V8: J43.3 U33.4(A2) ; port USBC_ALERT_N_1V8
USBC_ALERT_N_3V3: U33.1(B2) ; port USBC_ALERT_N_3V3
USBC_INT_B_1V8: J51.3 U33.5(A1) ; port USBC_INT_B_1V8
USBC_INT_B_3V3: U33.8(B1) ; port USBC_INT_B_3V3
XBEE_UART_CTS_1V8: J58.3 U35.4(A2) ; port XBEE_UART_CTS_1V8
XBEE_UART_CTS_3V3: U35.1(B2) ; port XBEE_UART_CTS_3V3
XBEE_UART_RTS_1V8: J59.3 U35.5(A1) ; port XBEE_UART_RTS_1V8
XBEE_UART_RTS_3V3: U35.8(B1) ; port XBEE_UART_RTS_3V3
XBEE_UART_RX_1V8: J54.3 U34.4(A2) ; port XBEE_UART_RX_1V8
XBEE_UART_RX_3V3: U34.1(B2) ; port XBEE_UART_RX_3V3
XBEE_UART_TX_1V8: J57.3 U34.5(A1) ; port XBEE_UART_TX_1V8
XBEE_UART_TX_3V3: U34.8(B1) ; port XBEE_UART_TX_3V3
NetR210_2: R210.2 U33.6(OE)
NetR211_2: R211.2 U34.6(OE)
NetR237_2: R237.2 U35.6(OE)

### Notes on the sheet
- (near J45) ENET2 shared lines
- UART7 shared lines

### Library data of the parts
C202-C207 = 1000006: CAP 100nF 16V 10% X7R 0402; Part_Type: Capacitor; Manufacturer: Murata; Manufacturer_Part_Number: GRM155R71C104KA88D; Digi_PN: 14050552; Component_Life_Cycle_State: CAD Reviewed; Area: 0,95; Tolerance: 10
J43 J45 J51-J62 = 1002832: as J64 on sheet 02 - Power, reset
R210 R211 R237 = 1000537: RES 10.0K OHM 1/10W 1% 0402 SMD; Part_Type: Resistor; Manufacturer: Panasonic - ECG; Manufacturer_Part_Number: ERJ-2RKF1002X; Digi_PN: 13051084; Component_Life_Cycle_State: CAD Reviewed; Area: 0,95; Power_WV_SRF: 100
U33-U35 = 1002597: IC TRANSLATING TXRX 8XSON; Manufacturer: NXP Semiconductors; Manufacturer_Part_Number: NTS0102GT,115; Digi_PN: 16000138; Component_Life_Cycle_State: Reviewed; Area: 3,9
